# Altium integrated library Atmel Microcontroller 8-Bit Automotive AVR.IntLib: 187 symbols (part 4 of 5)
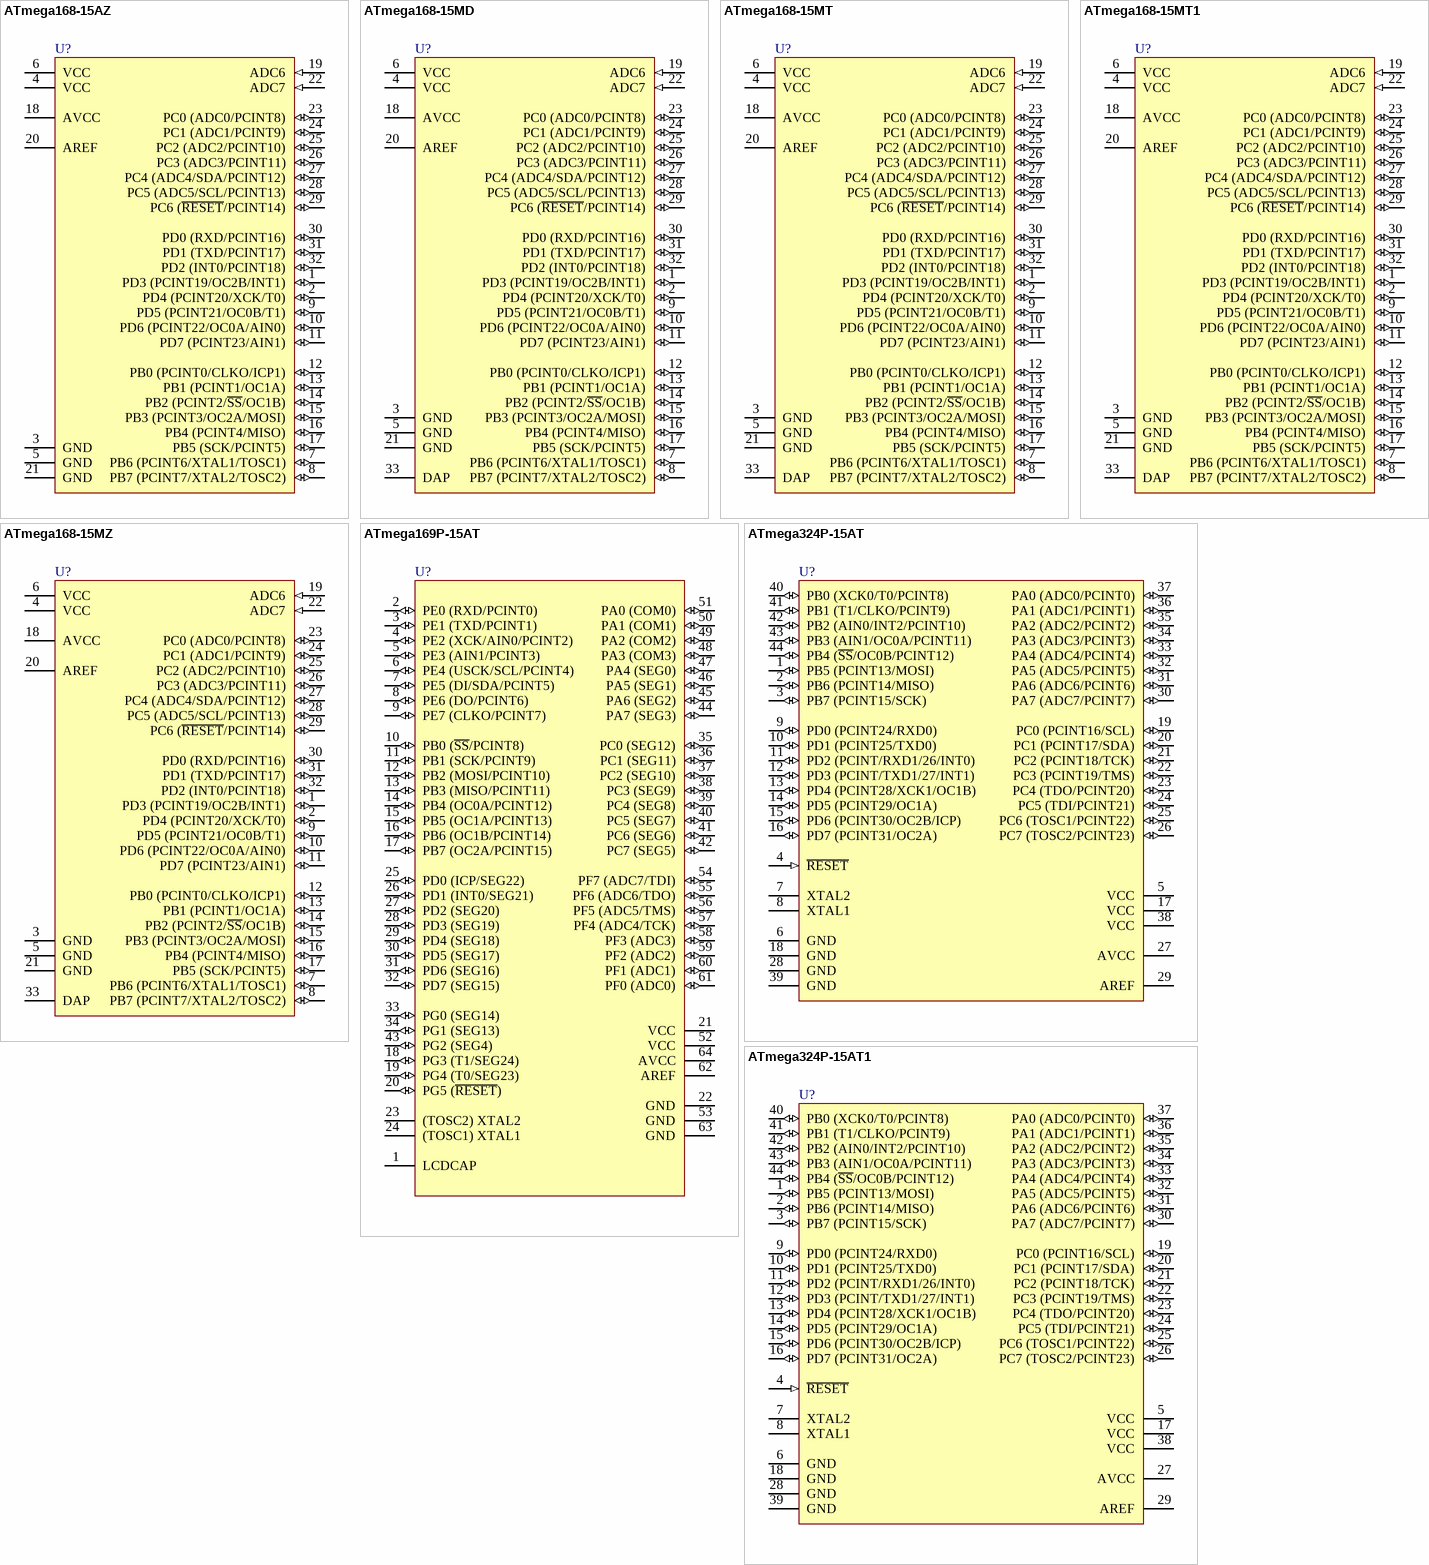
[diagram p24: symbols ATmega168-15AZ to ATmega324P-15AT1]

## ATmega168-15MT
designator U?
8-bit Automotive AVR Microcontroller, 16KB Flash, 512 Bytes EEPROM, 1KB SRAM, Automotive Grade (-40°C to +85°C), 32-Pin VQFN
footprint 32PN_N (QFN, 32-Leads, Body 5x5mm, Pitch 0.5mm, IPC Medium Density)
footprint 32PN_L (QFN, 32-Leads, Body 5x5mm, Pitch 0.5mm, IPC High Density)
footprint 32PN_M (QFN, 32-Leads, Body 5x5mm, Pitch 0.5mm, IPC Low Density)
pins: 1 PD3 (PCINT19/OC2B/INT1) (io), 2 PD4 (PCINT20/XCK/T0) (io), 3 GND (power), 4 VCC (power), 5 GND (power), 6 VCC (power), 7 PB6 (PCINT6/XTAL1/TOSC1) (io), 8 PB7 (PCINT7/XTAL2/TOSC2) (io), 9 PD5 (PCINT21/OC0B/T1) (io), 10 PD6 (PCINT22/OC0A/AIN0) (io), 11 PD7 (PCINT23/AIN1) (io), 12 PB0 (PCINT0/CLKO/ICP1) (io), 13 PB1 (PCINT1/OC1A) (io), 14 PB2 (PCINT2/~{SS}/OC1B) (io), 15 PB3 (PCINT3/OC2A/MOSI) (io), 16 PB4 (PCINT4/MISO) (io), 17 PB5 (SCK/PCINT5) (io), 18 AVCC (power), 19 ADC6 (in), 20 AREF, 21 GND (power), 22 ADC7 (in), 23 PC0 (ADC0/PCINT8) (io), 24 PC1 (ADC1/PCINT9) (io), 25 PC2 (ADC2/PCINT10) (io), 26 PC3 (ADC3/PCINT11) (io), 27 PC4 (ADC4/SDA/PCINT12) (io), 28 PC5 (ADC5/SCL/PCINT13) (io), 29 PC6 (~{RESET}/PCINT14) (io), 30 PD0 (RXD/PCINT16) (io), 31 PD1 (TXD/PCINT17) (io), 32 PD2 (INT0/PCINT18) (io), 33 DAP (power)

## ATmega168-15MT1
designator U?
8-bit Automotive AVR Microcontroller, 16KB Flash, 512 Bytes EEPROM, 1KB SRAM, Automotive Grade (-40°C to +105°C), 32-Pin VQFN
footprint 32PN_N (QFN, 32-Leads, Body 5x5mm, Pitch 0.5mm, IPC Medium Density)
footprint 32PN_L (QFN, 32-Leads, Body 5x5mm, Pitch 0.5mm, IPC High Density)
footprint 32PN_M (QFN, 32-Leads, Body 5x5mm, Pitch 0.5mm, IPC Low Density)
pins: 1 PD3 (PCINT19/OC2B/INT1) (io), 2 PD4 (PCINT20/XCK/T0) (io), 3 GND (power), 4 VCC (power), 5 GND (power), 6 VCC (power), 7 PB6 (PCINT6/XTAL1/TOSC1) (io), 8 PB7 (PCINT7/XTAL2/TOSC2) (io), 9 PD5 (PCINT21/OC0B/T1) (io), 10 PD6 (PCINT22/OC0A/AIN0) (io), 11 PD7 (PCINT23/AIN1) (io), 12 PB0 (PCINT0/CLKO/ICP1) (io), 13 PB1 (PCINT1/OC1A) (io), 14 PB2 (PCINT2/~{SS}/OC1B) (io), 15 PB3 (PCINT3/OC2A/MOSI) (io), 16 PB4 (PCINT4/MISO) (io), 17 PB5 (SCK/PCINT5) (io), 18 AVCC (power), 19 ADC6 (in), 20 AREF, 21 GND (power), 22 ADC7 (in), 23 PC0 (ADC0/PCINT8) (io), 24 PC1 (ADC1/PCINT9) (io), 25 PC2 (ADC2/PCINT10) (io), 26 PC3 (ADC3/PCINT11) (io), 27 PC4 (ADC4/SDA/PCINT12) (io), 28 PC5 (ADC5/SCL/PCINT13) (io), 29 PC6 (~{RESET}/PCINT14) (io), 30 PD0 (RXD/PCINT16) (io), 31 PD1 (TXD/PCINT17) (io), 32 PD2 (INT0/PCINT18) (io), 33 DAP (power)

## ATmega168-15MZ
designator U?
8-bit Automotive AVR Microcontroller, 16KB Flash, 512 Bytes EEPROM, 1KB SRAM, Automotive Grade (-40°C to 125°C), 32-Pin VQFN
footprint 32PN_N (QFN, 32-Leads, Body 5x5mm, Pitch 0.5mm, IPC Medium Density)
footprint 32PN_L (QFN, 32-Leads, Body 5x5mm, Pitch 0.5mm, IPC High Density)
footprint 32PN_M (QFN, 32-Leads, Body 5x5mm, Pitch 0.5mm, IPC Low Density)
pins: 1 PD3 (PCINT19/OC2B/INT1) (io), 2 PD4 (PCINT20/XCK/T0) (io), 3 GND (power), 4 VCC (power), 5 GND (power), 6 VCC (power), 7 PB6 (PCINT6/XTAL1/TOSC1) (io), 8 PB7 (PCINT7/XTAL2/TOSC2) (io), 9 PD5 (PCINT21/OC0B/T1) (io), 10 PD6 (PCINT22/OC0A/AIN0) (io), 11 PD7 (PCINT23/AIN1) (io), 12 PB0 (PCINT0/CLKO/ICP1) (io), 13 PB1 (PCINT1/OC1A) (io), 14 PB2 (PCINT2/~{SS}/OC1B) (io), 15 PB3 (PCINT3/OC2A/MOSI) (io), 16 PB4 (PCINT4/MISO) (io), 17 PB5 (SCK/PCINT5) (io), 18 AVCC (power), 19 ADC6 (in), 20 AREF, 21 GND (power), 22 ADC7 (in), 23 PC0 (ADC0/PCINT8) (io), 24 PC1 (ADC1/PCINT9) (io), 25 PC2 (ADC2/PCINT10) (io), 26 PC3 (ADC3/PCINT11) (io), 27 PC4 (ADC4/SDA/PCINT12) (io), 28 PC5 (ADC5/SCL/PCINT13) (io), 29 PC6 (~{RESET}/PCINT14) (io), 30 PD0 (RXD/PCINT16) (io), 31 PD1 (TXD/PCINT17) (io), 32 PD2 (INT0/PCINT18) (io), 33 DAP (power)

## ATmega169P-15AT
designator U?
8-bit Automotive AVR Microcontroller, 16KB Flash, 512 Bytes EEPROM, 1KB SRAM, Automotive Quality (-40°C to 85°C), 64-pin TQFP
footprint 64MD_N (Thin QFP, 64-Leads, Body 14x14mm, Pitch 0.8mm, IPC Medium Density)
footprint 64MD_L (Thin QFP, 64-Leads, Body 14x14mm, Pitch 0.8mm, IPC High Density)
footprint 64MD_M (Thin QFP, 64-Leads, Body 14x14mm, Pitch 0.8mm, IPC Low Density)
pins: 1 LCDCAP, 2 PE0 (RXD/PCINT0) (io), 3 PE1 (TXD/PCINT1) (io), 4 PE2 (XCK/AIN0/PCINT2) (io), 5 PE3 (AIN1/PCINT3) (io), 6 PE4 (USCK/SCL/PCINT4) (io), 7 PE5 (DI/SDA/PCINT5) (io), 8 PE6 (DO/PCINT6) (io), 9 PE7 (CLKO/PCINT7) (io), 10 PB0 (~{SS}/PCINT8) (io), 11 PB1 (SCK/PCINT9) (io), 12 PB2 (MOSI/PCINT10) (io), 13 PB3 (MISO/PCINT11) (io), 14 PB4 (OC0A/PCINT12) (io), 15 PB5 (OC1A/PCINT13) (io), 16 PB6 (OC1B/PCINT14) (io), 17 PB7 (OC2A/PCINT15) (io), 18 PG3 (T1/SEG24) (io), 19 PG4 (T0/SEG23) (io), 20 PG5 (~{RESET}) (io), 21 VCC (power), 22 GND (power), 23 (TOSC2) XTAL2, 24 (TOSC1) XTAL1, 25 PD0 (ICP/SEG22) (io), 26 PD1 (INT0/SEG21) (io), 27 PD2 (SEG20) (io), 28 PD3 (SEG19) (io), 29 PD4 (SEG18) (io), 30 PD5 (SEG17) (io), 31 PD6 (SEG16) (io), 32 PD7 (SEG15) (io), 33 PG0 (SEG14) (io), 34 PG1 (SEG13) (io), 35 PC0 (SEG12) (io), 36 PC1 (SEG11) (io), 37 PC2 (SEG10) (io), 38 PC3 (SEG9) (io), 39 PC4 (SEG8) (io), 40 PC5 (SEG7) (io), 41 PC6 (SEG6) (io), 42 PC7 (SEG5) (io), 43 PG2 (SEG4) (io), 44 PA7 (SEG3) (io), 45 PA6 (SEG2) (io), 46 PA5 (SEG1) (io), 47 PA4 (SEG0) (io), 48 PA3 (COM3) (io), 49 PA2 (COM2) (io), 50 PA1 (COM1) (io), 51 PA0 (COM0) (io), 52 VCC (power), 53 GND (power), 54 PF7 (ADC7/TDI) (io), 55 PF6 (ADC6/TDO) (io), 56 PF5 (ADC5/TMS) (io), 57 PF4 (ADC4/TCK) (io), 58 PF3 (ADC3) (io), 59 PF2 (ADC2) (io), 60 PF1 (ADC1) (io), 61 PF0 (ADC0) (io), 62 AREF, 63 GND (power), 64 AVCC (power)

## ATmega324P-15AT
designator U?
8-bit Automotive AVR Microcontroller, 32KB Flash, 1KB EEPROM, 2KB SRAM, Automotive Quality (-40°C to +85°C), 44-Pin TQFP
footprint 44ML_N (Thin QFP, 44-Leads, Body 10x10mm, Pitch 0.8mm, IPC Medium Density)
footprint 44ML_L (Thin QFP, 44-Leads, Body 10x10mm, Pitch 0.8mm, IPC High Density)
footprint 44ML_M (Thin QFP, 44-Leads, Body 10x10mm, Pitch 0.8mm, IPC Low Density)
pins: 1 PB5 (PCINT13/MOSI) (io), 2 PB6 (PCINT14/MISO) (io), 3 PB7 (PCINT15/SCK) (io), 4 ~{RESET} (in), 5 VCC (power), 6 GND (power), 7 XTAL2, 8 XTAL1, 9 PD0 (PCINT24/RXD0) (io), 10 PD1 (PCINT25/TXD0) (io), 11 PD2 (PCINT/RXD1/26/INT0) (io), 12 PD3 (PCINT/TXD1/27/INT1) (io), 13 PD4 (PCINT28/XCK1/OC1B) (io), 14 PD5 (PCINT29/OC1A) (io), 15 PD6 (PCINT30/OC2B/ICP) (io), 16 PD7 (PCINT31/OC2A) (io), 17 VCC (power), 18 GND (power), 19 PC0 (PCINT16/SCL) (io), 20 PC1 (PCINT17/SDA) (io), 21 PC2 (PCINT18/TCK) (io), 22 PC3 (PCINT19/TMS) (io), 23 PC4 (TDO/PCINT20) (io), 24 PC5 (TDI/PCINT21) (io), 25 PC6 (TOSC1/PCINT22) (io), 26 PC7 (TOSC2/PCINT23) (io), 27 AVCC (power), 28 GND (power), 29 AREF (power), 30 PA7 (ADC7/PCINT7) (io), 31 PA6 (ADC6/PCINT6) (io), 32 PA5 (ADC5/PCINT5) (io), 33 PA4 (ADC4/PCINT4) (io), 34 PA3 (ADC3/PCINT3) (io), 35 PA2 (ADC2/PCINT2) (io), 36 PA1 (ADC1/PCINT1) (io), 37 PA0 (ADC0/PCINT0) (io), 38 VCC (power), 39 GND (power), 40 PB0 (XCK0/T0/PCINT8) (io), 41 PB1 (T1/CLKO/PCINT9) (io), 42 PB2 (AIN0/INT2/PCINT10) (io), 43 PB3 (AIN1/OC0A/PCINT11) (io), 44 PB4 (~{SS}/OC0B/PCINT12) (io)

## ATmega324P-15AT1
designator U?
8-bit Automotive AVR Microcontroller, 32KB Flash, 1KB EEPROM, 2KB SRAM, Reduced Automotive Grade (-40°C to +105°C), 44-Pin TQFP
footprint 44ML_N (Thin QFP, 44-Leads, Body 10x10mm, Pitch 0.8mm, IPC Medium Density)
footprint 44ML_L (Thin QFP, 44-Leads, Body 10x10mm, Pitch 0.8mm, IPC High Density)
footprint 44ML_M (Thin QFP, 44-Leads, Body 10x10mm, Pitch 0.8mm, IPC Low Density)
pins: 1 PB5 (PCINT13/MOSI) (io), 2 PB6 (PCINT14/MISO) (io), 3 PB7 (PCINT15/SCK) (io), 4 ~{RESET} (in), 5 VCC (power), 6 GND (power), 7 XTAL2, 8 XTAL1, 9 PD0 (PCINT24/RXD0) (io), 10 PD1 (PCINT25/TXD0) (io), 11 PD2 (PCINT/RXD1/26/INT0) (io), 12 PD3 (PCINT/TXD1/27/INT1) (io), 13 PD4 (PCINT28/XCK1/OC1B) (io), 14 PD5 (PCINT29/OC1A) (io), 15 PD6 (PCINT30/OC2B/ICP) (io), 16 PD7 (PCINT31/OC2A) (io), 17 VCC (power), 18 GND (power), 19 PC0 (PCINT16/SCL) (io), 20 PC1 (PCINT17/SDA) (io), 21 PC2 (PCINT18/TCK) (io), 22 PC3 (PCINT19/TMS) (io), 23 PC4 (TDO/PCINT20) (io), 24 PC5 (TDI/PCINT21) (io), 25 PC6 (TOSC1/PCINT22) (io), 26 PC7 (TOSC2/PCINT23) (io), 27 AVCC (power), 28 GND (power), 29 AREF (power), 30 PA7 (ADC7/PCINT7) (io), 31 PA6 (ADC6/PCINT6) (io), 32 PA5 (ADC5/PCINT5) (io), 33 PA4 (ADC4/PCINT4) (io), 34 PA3 (ADC3/PCINT3) (io), 35 PA2 (ADC2/PCINT2) (io), 36 PA1 (ADC1/PCINT1) (io), 37 PA0 (ADC0/PCINT0) (io), 38 VCC (power), 39 GND (power), 40 PB0 (XCK0/T0/PCINT8) (io), 41 PB1 (T1/CLKO/PCINT9) (io), 42 PB2 (AIN0/INT2/PCINT10) (io), 43 PB3 (AIN1/OC0A/PCINT11) (io), 44 PB4 (~{SS}/OC0B/PCINT12) (io)

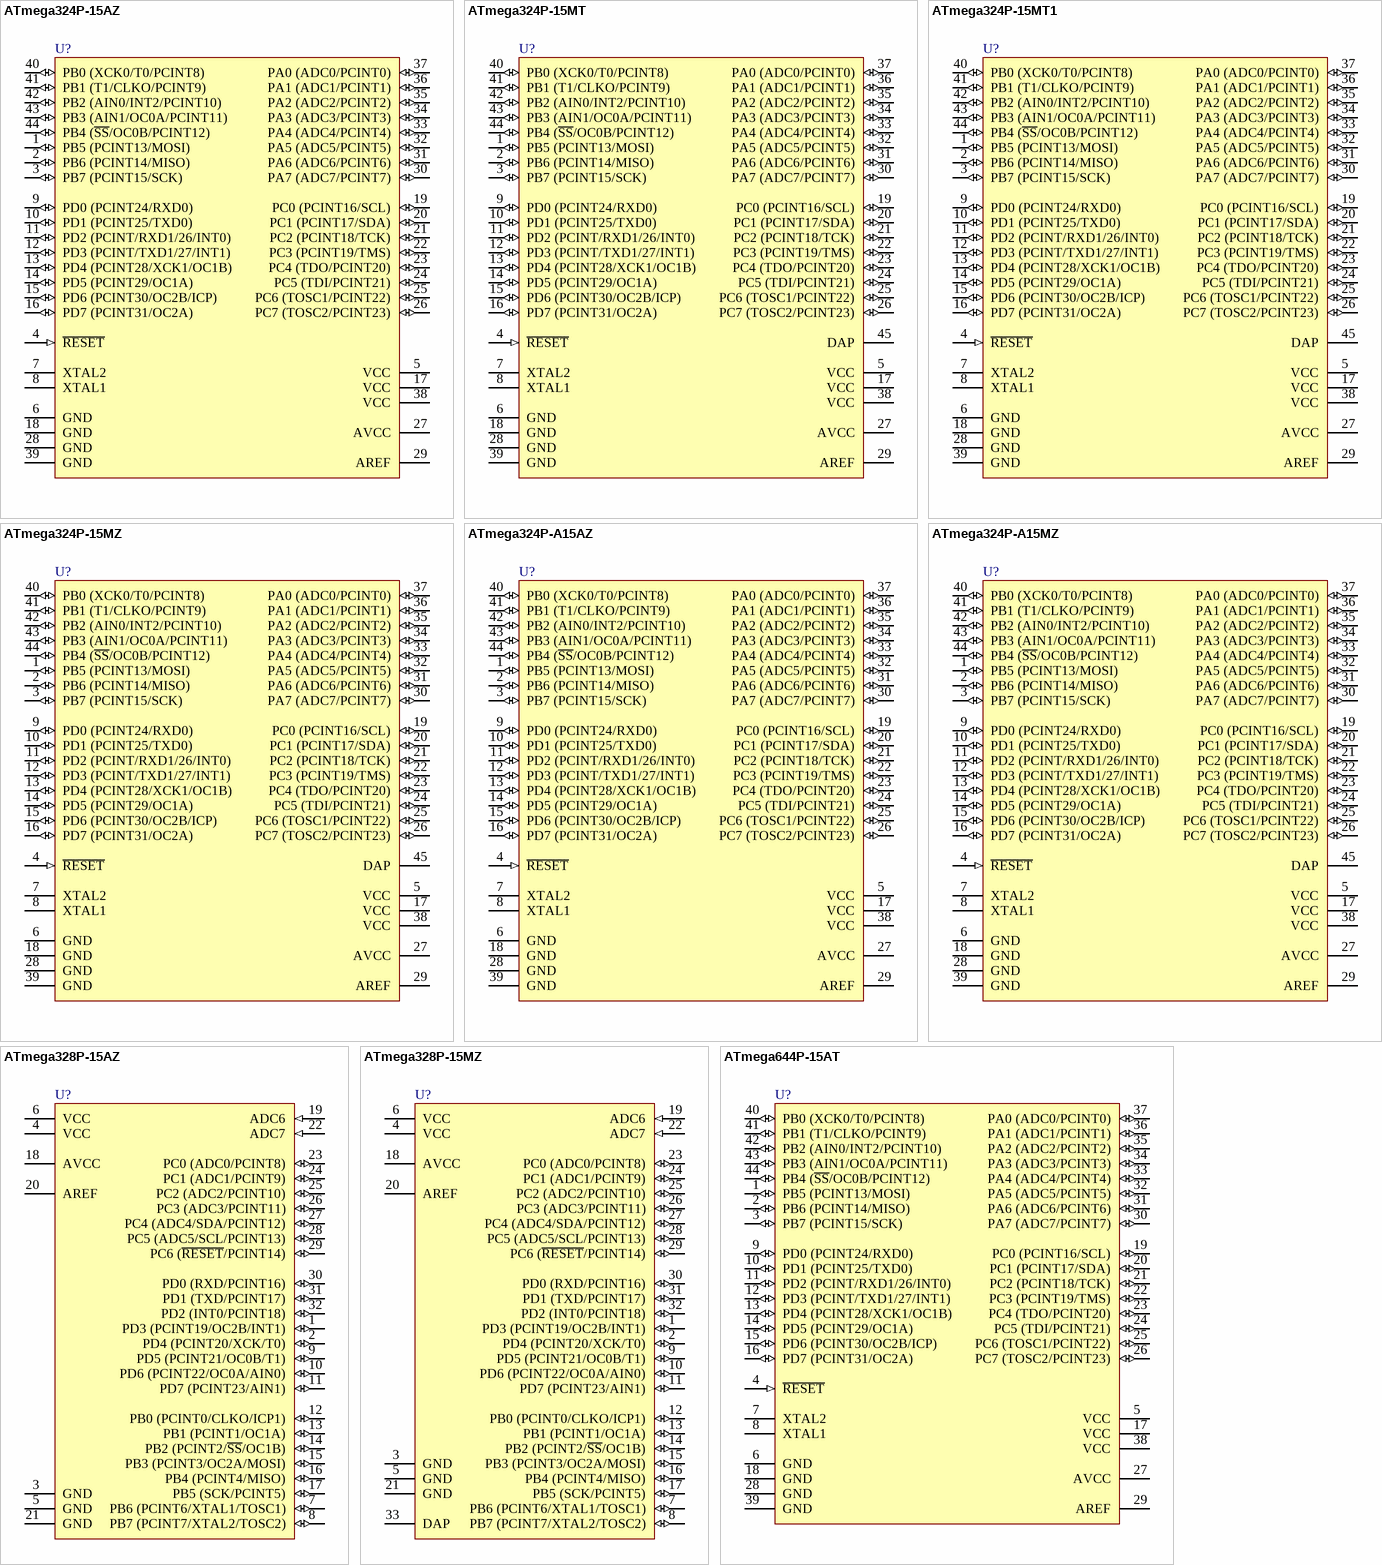
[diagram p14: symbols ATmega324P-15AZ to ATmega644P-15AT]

## ATmega324P-15AZ
designator U?
8-bit Automotive AVR Microcontroller, 32KB Flash, 1KB EEPROM, 2KB SRAM, Automotive Grade (-40°C to +125°C), 44-Pin TQFP
footprint 44ML_N (Thin QFP, 44-Leads, Body 10x10mm, Pitch 0.8mm, IPC Medium Density)
footprint 44ML_L (Thin QFP, 44-Leads, Body 10x10mm, Pitch 0.8mm, IPC High Density)
footprint 44ML_M (Thin QFP, 44-Leads, Body 10x10mm, Pitch 0.8mm, IPC Low Density)
pins: 1 PB5 (PCINT13/MOSI) (io), 2 PB6 (PCINT14/MISO) (io), 3 PB7 (PCINT15/SCK) (io), 4 ~{RESET} (in), 5 VCC (power), 6 GND (power), 7 XTAL2, 8 XTAL1, 9 PD0 (PCINT24/RXD0) (io), 10 PD1 (PCINT25/TXD0) (io), 11 PD2 (PCINT/RXD1/26/INT0) (io), 12 PD3 (PCINT/TXD1/27/INT1) (io), 13 PD4 (PCINT28/XCK1/OC1B) (io), 14 PD5 (PCINT29/OC1A) (io), 15 PD6 (PCINT30/OC2B/ICP) (io), 16 PD7 (PCINT31/OC2A) (io), 17 VCC (power), 18 GND (power), 19 PC0 (PCINT16/SCL) (io), 20 PC1 (PCINT17/SDA) (io), 21 PC2 (PCINT18/TCK) (io), 22 PC3 (PCINT19/TMS) (io), 23 PC4 (TDO/PCINT20) (io), 24 PC5 (TDI/PCINT21) (io), 25 PC6 (TOSC1/PCINT22) (io), 26 PC7 (TOSC2/PCINT23) (io), 27 AVCC (power), 28 GND (power), 29 AREF (power), 30 PA7 (ADC7/PCINT7) (io), 31 PA6 (ADC6/PCINT6) (io), 32 PA5 (ADC5/PCINT5) (io), 33 PA4 (ADC4/PCINT4) (io), 34 PA3 (ADC3/PCINT3) (io), 35 PA2 (ADC2/PCINT2) (io), 36 PA1 (ADC1/PCINT1) (io), 37 PA0 (ADC0/PCINT0) (io), 38 VCC (power), 39 GND (power), 40 PB0 (XCK0/T0/PCINT8) (io), 41 PB1 (T1/CLKO/PCINT9) (io), 42 PB2 (AIN0/INT2/PCINT10) (io), 43 PB3 (AIN1/OC0A/PCINT11) (io), 44 PB4 (~{SS}/OC0B/PCINT12) (io)

## ATmega324P-15MT
designator U?
8-bit Automotive AVR Microcontroller, 32KB Flash, 1KB EEPROM, 2KB SRAM, Automotive Quality (-40°C to +85°C), 44-Pin VQFN
footprint 44PW_N (QFN, 44-Leads, Body 7x7mm, Pitch 0.5mm, IPC Medium Density)
footprint 44PW_L (QFN, 44-Leads, Body 7x7mm, Pitch 0.5mm, IPC High Density)
footprint 44PW_M (QFN, 44-Leads, Body 7x7mm, Pitch 0.5mm, IPC Low Density)
pins: 1 PB5 (PCINT13/MOSI) (io), 2 PB6 (PCINT14/MISO) (io), 3 PB7 (PCINT15/SCK) (io), 4 ~{RESET} (in), 5 VCC (power), 6 GND (power), 7 XTAL2, 8 XTAL1, 9 PD0 (PCINT24/RXD0) (io), 10 PD1 (PCINT25/TXD0) (io), 11 PD2 (PCINT/RXD1/26/INT0) (io), 12 PD3 (PCINT/TXD1/27/INT1) (io), 13 PD4 (PCINT28/XCK1/OC1B) (io), 14 PD5 (PCINT29/OC1A) (io), 15 PD6 (PCINT30/OC2B/ICP) (io), 16 PD7 (PCINT31/OC2A) (io), 17 VCC (power), 18 GND (power), 19 PC0 (PCINT16/SCL) (io), 20 PC1 (PCINT17/SDA) (io), 21 PC2 (PCINT18/TCK) (io), 22 PC3 (PCINT19/TMS) (io), 23 PC4 (TDO/PCINT20) (io), 24 PC5 (TDI/PCINT21) (io), 25 PC6 (TOSC1/PCINT22) (io), 26 PC7 (TOSC2/PCINT23) (io), 27 AVCC (power), 28 GND (power), 29 AREF, 30 PA7 (ADC7/PCINT7) (io), 31 PA6 (ADC6/PCINT6) (io), 32 PA5 (ADC5/PCINT5) (io), 33 PA4 (ADC4/PCINT4) (io), 34 PA3 (ADC3/PCINT3) (io), 35 PA2 (ADC2/PCINT2) (io), 36 PA1 (ADC1/PCINT1) (io), 37 PA0 (ADC0/PCINT0) (io), 38 VCC (power), 39 GND (power), 40 PB0 (XCK0/T0/PCINT8) (io), 41 PB1 (T1/CLKO/PCINT9) (io), 42 PB2 (AIN0/INT2/PCINT10) (io), 43 PB3 (AIN1/OC0A/PCINT11) (io), 44 PB4 (~{SS}/OC0B/PCINT12) (io), 45 DAP (power)

## ATmega324P-15MT1
designator U?
8-bit Automotive AVR Microcontroller, 32KB Flash, 1KB EEPROM, 2KB SRAM, Reduced Automotive Grade (-40°C to +105°C), 44-Pin VQFN
footprint 44PW_N (QFN, 44-Leads, Body 7x7mm, Pitch 0.5mm, IPC Medium Density)
footprint 44PW_L (QFN, 44-Leads, Body 7x7mm, Pitch 0.5mm, IPC High Density)
footprint 44PW_M (QFN, 44-Leads, Body 7x7mm, Pitch 0.5mm, IPC Low Density)
pins: 1 PB5 (PCINT13/MOSI) (io), 2 PB6 (PCINT14/MISO) (io), 3 PB7 (PCINT15/SCK) (io), 4 ~{RESET} (in), 5 VCC (power), 6 GND (power), 7 XTAL2, 8 XTAL1, 9 PD0 (PCINT24/RXD0) (io), 10 PD1 (PCINT25/TXD0) (io), 11 PD2 (PCINT/RXD1/26/INT0) (io), 12 PD3 (PCINT/TXD1/27/INT1) (io), 13 PD4 (PCINT28/XCK1/OC1B) (io), 14 PD5 (PCINT29/OC1A) (io), 15 PD6 (PCINT30/OC2B/ICP) (io), 16 PD7 (PCINT31/OC2A) (io), 17 VCC (power), 18 GND (power), 19 PC0 (PCINT16/SCL) (io), 20 PC1 (PCINT17/SDA) (io), 21 PC2 (PCINT18/TCK) (io), 22 PC3 (PCINT19/TMS) (io), 23 PC4 (TDO/PCINT20) (io), 24 PC5 (TDI/PCINT21) (io), 25 PC6 (TOSC1/PCINT22) (io), 26 PC7 (TOSC2/PCINT23) (io), 27 AVCC (power), 28 GND (power), 29 AREF, 30 PA7 (ADC7/PCINT7) (io), 31 PA6 (ADC6/PCINT6) (io), 32 PA5 (ADC5/PCINT5) (io), 33 PA4 (ADC4/PCINT4) (io), 34 PA3 (ADC3/PCINT3) (io), 35 PA2 (ADC2/PCINT2) (io), 36 PA1 (ADC1/PCINT1) (io), 37 PA0 (ADC0/PCINT0) (io), 38 VCC (power), 39 GND (power), 40 PB0 (XCK0/T0/PCINT8) (io), 41 PB1 (T1/CLKO/PCINT9) (io), 42 PB2 (AIN0/INT2/PCINT10) (io), 43 PB3 (AIN1/OC0A/PCINT11) (io), 44 PB4 (~{SS}/OC0B/PCINT12) (io), 45 DAP (power)

## ATmega324P-15MZ
designator U?
8-bit Automotive AVR Microcontroller, 32KB Flash, 1KB EEPROM, 2KB SRAM, Automotive Grade (-40°C to +125°C), 44-Pin VQFN
footprint 44PW_N (QFN, 44-Leads, Body 7x7mm, Pitch 0.5mm, IPC Medium Density)
footprint 44PW_L (QFN, 44-Leads, Body 7x7mm, Pitch 0.5mm, IPC High Density)
footprint 44PW_M (QFN, 44-Leads, Body 7x7mm, Pitch 0.5mm, IPC Low Density)
pins: 1 PB5 (PCINT13/MOSI) (io), 2 PB6 (PCINT14/MISO) (io), 3 PB7 (PCINT15/SCK) (io), 4 ~{RESET} (in), 5 VCC (power), 6 GND (power), 7 XTAL2, 8 XTAL1, 9 PD0 (PCINT24/RXD0) (io), 10 PD1 (PCINT25/TXD0) (io), 11 PD2 (PCINT/RXD1/26/INT0) (io), 12 PD3 (PCINT/TXD1/27/INT1) (io), 13 PD4 (PCINT28/XCK1/OC1B) (io), 14 PD5 (PCINT29/OC1A) (io), 15 PD6 (PCINT30/OC2B/ICP) (io), 16 PD7 (PCINT31/OC2A) (io), 17 VCC (power), 18 GND (power), 19 PC0 (PCINT16/SCL) (io), 20 PC1 (PCINT17/SDA) (io), 21 PC2 (PCINT18/TCK) (io), 22 PC3 (PCINT19/TMS) (io), 23 PC4 (TDO/PCINT20) (io), 24 PC5 (TDI/PCINT21) (io), 25 PC6 (TOSC1/PCINT22) (io), 26 PC7 (TOSC2/PCINT23) (io), 27 AVCC (power), 28 GND (power), 29 AREF, 30 PA7 (ADC7/PCINT7) (io), 31 PA6 (ADC6/PCINT6) (io), 32 PA5 (ADC5/PCINT5) (io), 33 PA4 (ADC4/PCINT4) (io), 34 PA3 (ADC3/PCINT3) (io), 35 PA2 (ADC2/PCINT2) (io), 36 PA1 (ADC1/PCINT1) (io), 37 PA0 (ADC0/PCINT0) (io), 38 VCC (power), 39 GND (power), 40 PB0 (XCK0/T0/PCINT8) (io), 41 PB1 (T1/CLKO/PCINT9) (io), 42 PB2 (AIN0/INT2/PCINT10) (io), 43 PB3 (AIN1/OC0A/PCINT11) (io), 44 PB4 (~{SS}/OC0B/PCINT12) (io), 45 DAP (power)

## ATmega324P-A15AZ
designator U?
8-bit Automotive AVR Microcontroller, 32KB Flash, 1KB EEPROM, 2KB SRAM, Automotive Grade (-40°C to +125°C), 44-Pin TQFP
footprint 44ML_N (Thin QFP, 44-Leads, Body 10x10mm, Pitch 0.8mm, IPC Medium Density)
footprint 44ML_L (Thin QFP, 44-Leads, Body 10x10mm, Pitch 0.8mm, IPC High Density)
footprint 44ML_M (Thin QFP, 44-Leads, Body 10x10mm, Pitch 0.8mm, IPC Low Density)
pins: 1 PB5 (PCINT13/MOSI) (io), 2 PB6 (PCINT14/MISO) (io), 3 PB7 (PCINT15/SCK) (io), 4 ~{RESET} (in), 5 VCC (power), 6 GND (power), 7 XTAL2, 8 XTAL1, 9 PD0 (PCINT24/RXD0) (io), 10 PD1 (PCINT25/TXD0) (io), 11 PD2 (PCINT/RXD1/26/INT0) (io), 12 PD3 (PCINT/TXD1/27/INT1) (io), 13 PD4 (PCINT28/XCK1/OC1B) (io), 14 PD5 (PCINT29/OC1A) (io), 15 PD6 (PCINT30/OC2B/ICP) (io), 16 PD7 (PCINT31/OC2A) (io), 17 VCC (power), 18 GND (power), 19 PC0 (PCINT16/SCL) (io), 20 PC1 (PCINT17/SDA) (io), 21 PC2 (PCINT18/TCK) (io), 22 PC3 (PCINT19/TMS) (io), 23 PC4 (TDO/PCINT20) (io), 24 PC5 (TDI/PCINT21) (io), 25 PC6 (TOSC1/PCINT22) (io), 26 PC7 (TOSC2/PCINT23) (io), 27 AVCC (power), 28 GND (power), 29 AREF (power), 30 PA7 (ADC7/PCINT7) (io), 31 PA6 (ADC6/PCINT6) (io), 32 PA5 (ADC5/PCINT5) (io), 33 PA4 (ADC4/PCINT4) (io), 34 PA3 (ADC3/PCINT3) (io), 35 PA2 (ADC2/PCINT2) (io), 36 PA1 (ADC1/PCINT1) (io), 37 PA0 (ADC0/PCINT0) (io), 38 VCC (power), 39 GND (power), 40 PB0 (XCK0/T0/PCINT8) (io), 41 PB1 (T1/CLKO/PCINT9) (io), 42 PB2 (AIN0/INT2/PCINT10) (io), 43 PB3 (AIN1/OC0A/PCINT11) (io), 44 PB4 (~{SS}/OC0B/PCINT12) (io)

## ATmega324P-A15MZ
designator U?
8-bit Automotive AVR Microcontroller, 32KB Flash, 1KB EEPROM, 2KB SRAM, Automotive Grade (-40°C to +125°C), 44-Pin VQFN
footprint 44PW_N (QFN, 44-Leads, Body 7x7mm, Pitch 0.5mm, IPC Medium Density)
footprint 44PW_L (QFN, 44-Leads, Body 7x7mm, Pitch 0.5mm, IPC High Density)
footprint 44PW_M (QFN, 44-Leads, Body 7x7mm, Pitch 0.5mm, IPC Low Density)
pins: 1 PB5 (PCINT13/MOSI) (io), 2 PB6 (PCINT14/MISO) (io), 3 PB7 (PCINT15/SCK) (io), 4 ~{RESET} (in), 5 VCC (power), 6 GND (power), 7 XTAL2, 8 XTAL1, 9 PD0 (PCINT24/RXD0) (io), 10 PD1 (PCINT25/TXD0) (io), 11 PD2 (PCINT/RXD1/26/INT0) (io), 12 PD3 (PCINT/TXD1/27/INT1) (io), 13 PD4 (PCINT28/XCK1/OC1B) (io), 14 PD5 (PCINT29/OC1A) (io), 15 PD6 (PCINT30/OC2B/ICP) (io), 16 PD7 (PCINT31/OC2A) (io), 17 VCC (power), 18 GND (power), 19 PC0 (PCINT16/SCL) (io), 20 PC1 (PCINT17/SDA) (io), 21 PC2 (PCINT18/TCK) (io), 22 PC3 (PCINT19/TMS) (io), 23 PC4 (TDO/PCINT20) (io), 24 PC5 (TDI/PCINT21) (io), 25 PC6 (TOSC1/PCINT22) (io), 26 PC7 (TOSC2/PCINT23) (io), 27 AVCC (power), 28 GND (power), 29 AREF, 30 PA7 (ADC7/PCINT7) (io), 31 PA6 (ADC6/PCINT6) (io), 32 PA5 (ADC5/PCINT5) (io), 33 PA4 (ADC4/PCINT4) (io), 34 PA3 (ADC3/PCINT3) (io), 35 PA2 (ADC2/PCINT2) (io), 36 PA1 (ADC1/PCINT1) (io), 37 PA0 (ADC0/PCINT0) (io), 38 VCC (power), 39 GND (power), 40 PB0 (XCK0/T0/PCINT8) (io), 41 PB1 (T1/CLKO/PCINT9) (io), 42 PB2 (AIN0/INT2/PCINT10) (io), 43 PB3 (AIN1/OC0A/PCINT11) (io), 44 PB4 (~{SS}/OC0B/PCINT12) (io), 45 DAP (power)

## ATmega328P-15AZ
designator U?
8-bit Automotive AVR Microcontroller, 32KB Flash, 1KB EEPROM, 2KB SRAM, 23 GPIO pins, Automotive Grade (-40°C to +125°C), 32-Pin TQFP
footprint 32MA_N (Thin QFP, 32-Leads, Body 7x7mm, Pitch 0.8mm, IPC Medium Density)
footprint 32MA_L (Thin QFP, 32-Leads, Body 7x7mm, Pitch 0.8mm, IPC High Density)
footprint 32MA_M (Thin QFP, 32-Leads, Body 7x7mm, Pitch 0.8mm, IPC Low Density)
pins: 1 PD3 (PCINT19/OC2B/INT1) (io), 2 PD4 (PCINT20/XCK/T0) (io), 3 GND (power), 4 VCC (power), 5 GND (power), 6 VCC (power), 7 PB6 (PCINT6/XTAL1/TOSC1) (io), 8 PB7 (PCINT7/XTAL2/TOSC2) (io), 9 PD5 (PCINT21/OC0B/T1) (io), 10 PD6 (PCINT22/OC0A/AIN0) (io), 11 PD7 (PCINT23/AIN1) (io), 12 PB0 (PCINT0/CLKO/ICP1) (io), 13 PB1 (PCINT1/OC1A) (io), 14 PB2 (PCINT2/~{SS}/OC1B) (io), 15 PB3 (PCINT3/OC2A/MOSI) (io), 16 PB4 (PCINT4/MISO) (io), 17 PB5 (SCK/PCINT5) (io), 18 AVCC (power), 19 ADC6 (in), 20 AREF, 21 GND (power), 22 ADC7 (in), 23 PC0 (ADC0/PCINT8) (io), 24 PC1 (ADC1/PCINT9) (io), 25 PC2 (ADC2/PCINT10) (io), 26 PC3 (ADC3/PCINT11) (io), 27 PC4 (ADC4/SDA/PCINT12) (io), 28 PC5 (ADC5/SCL/PCINT13) (io), 29 PC6 (~{RESET}/PCINT14) (io), 30 PD0 (RXD/PCINT16) (io), 31 PD1 (TXD/PCINT17) (io), 32 PD2 (INT0/PCINT18) (io)

## ATmega328P-15MZ
designator U?
8-bit Automotive AVR Microcontroller, 32KB Flash, 1KB EEPROM, 2KB SRAM, 23 GPIO pins, Automotive Grade (-40°C to +125°C), 32-Pin VQFN
footprint 32PN_N (QFN, 32-Leads, Body 5x5mm, Pitch 0.5mm, IPC Medium Density)
footprint 32PN_L (QFN, 32-Leads, Body 5x5mm, Pitch 0.5mm, IPC High Density)
footprint 32PN_M (QFN, 32-Leads, Body 5x5mm, Pitch 0.5mm, IPC Low Density)
pins: 1 PD3 (PCINT19/OC2B/INT1) (io), 2 PD4 (PCINT20/XCK/T0) (io), 3 GND (power), 4 VCC (power), 5 GND (power), 6 VCC (power), 7 PB6 (PCINT6/XTAL1/TOSC1) (io), 8 PB7 (PCINT7/XTAL2/TOSC2) (io), 9 PD5 (PCINT21/OC0B/T1) (io), 10 PD6 (PCINT22/OC0A/AIN0) (io), 11 PD7 (PCINT23/AIN1) (io), 12 PB0 (PCINT0/CLKO/ICP1) (io), 13 PB1 (PCINT1/OC1A) (io), 14 PB2 (PCINT2/~{SS}/OC1B) (io), 15 PB3 (PCINT3/OC2A/MOSI) (io), 16 PB4 (PCINT4/MISO) (io), 17 PB5 (SCK/PCINT5) (io), 18 AVCC (power), 19 ADC6 (in), 20 AREF, 21 GND (power), 22 ADC7 (in), 23 PC0 (ADC0/PCINT8) (io), 24 PC1 (ADC1/PCINT9) (io), 25 PC2 (ADC2/PCINT10) (io), 26 PC3 (ADC3/PCINT11) (io), 27 PC4 (ADC4/SDA/PCINT12) (io), 28 PC5 (ADC5/SCL/PCINT13) (io), 29 PC6 (~{RESET}/PCINT14) (io), 30 PD0 (RXD/PCINT16) (io), 31 PD1 (TXD/PCINT17) (io), 32 PD2 (INT0/PCINT18) (io), 33 DAP (power)

## ATmega644P-15AT
designator U?
8-bit Automotive AVR Microcontroller, 64KB Flash, 2KB EEPROM, 4KB SRAM, Automotive Quality (-40°C to +85°C), 44-Pin TQFP
footprint 44ML_N (Thin QFP, 44-Leads, Body 10x10mm, Pitch 0.8mm, IPC Medium Density)
footprint 44ML_L (Thin QFP, 44-Leads, Body 10x10mm, Pitch 0.8mm, IPC High Density)
footprint 44ML_M (Thin QFP, 44-Leads, Body 10x10mm, Pitch 0.8mm, IPC Low Density)
pins: 1 PB5 (PCINT13/MOSI) (io), 2 PB6 (PCINT14/MISO) (io), 3 PB7 (PCINT15/SCK) (io), 4 ~{RESET} (in), 5 VCC (power), 6 GND (power), 7 XTAL2, 8 XTAL1, 9 PD0 (PCINT24/RXD0) (io), 10 PD1 (PCINT25/TXD0) (io), 11 PD2 (PCINT/RXD1/26/INT0) (io), 12 PD3 (PCINT/TXD1/27/INT1) (io), 13 PD4 (PCINT28/XCK1/OC1B) (io), 14 PD5 (PCINT29/OC1A) (io), 15 PD6 (PCINT30/OC2B/ICP) (io), 16 PD7 (PCINT31/OC2A) (io), 17 VCC (power), 18 GND (power), 19 PC0 (PCINT16/SCL) (io), 20 PC1 (PCINT17/SDA) (io), 21 PC2 (PCINT18/TCK) (io), 22 PC3 (PCINT19/TMS) (io), 23 PC4 (TDO/PCINT20) (io), 24 PC5 (TDI/PCINT21) (io), 25 PC6 (TOSC1/PCINT22) (io), 26 PC7 (TOSC2/PCINT23) (io), 27 AVCC (power), 28 GND (power), 29 AREF (power), 30 PA7 (ADC7/PCINT7) (io), 31 PA6 (ADC6/PCINT6) (io), 32 PA5 (ADC5/PCINT5) (io), 33 PA4 (ADC4/PCINT4) (io), 34 PA3 (ADC3/PCINT3) (io), 35 PA2 (ADC2/PCINT2) (io), 36 PA1 (ADC1/PCINT1) (io), 37 PA0 (ADC0/PCINT0) (io), 38 VCC (power), 39 GND (power), 40 PB0 (XCK0/T0/PCINT8) (io), 41 PB1 (T1/CLKO/PCINT9) (io), 42 PB2 (AIN0/INT2/PCINT10) (io), 43 PB3 (AIN1/OC0A/PCINT11) (io), 44 PB4 (~{SS}/OC0B/PCINT12) (io)

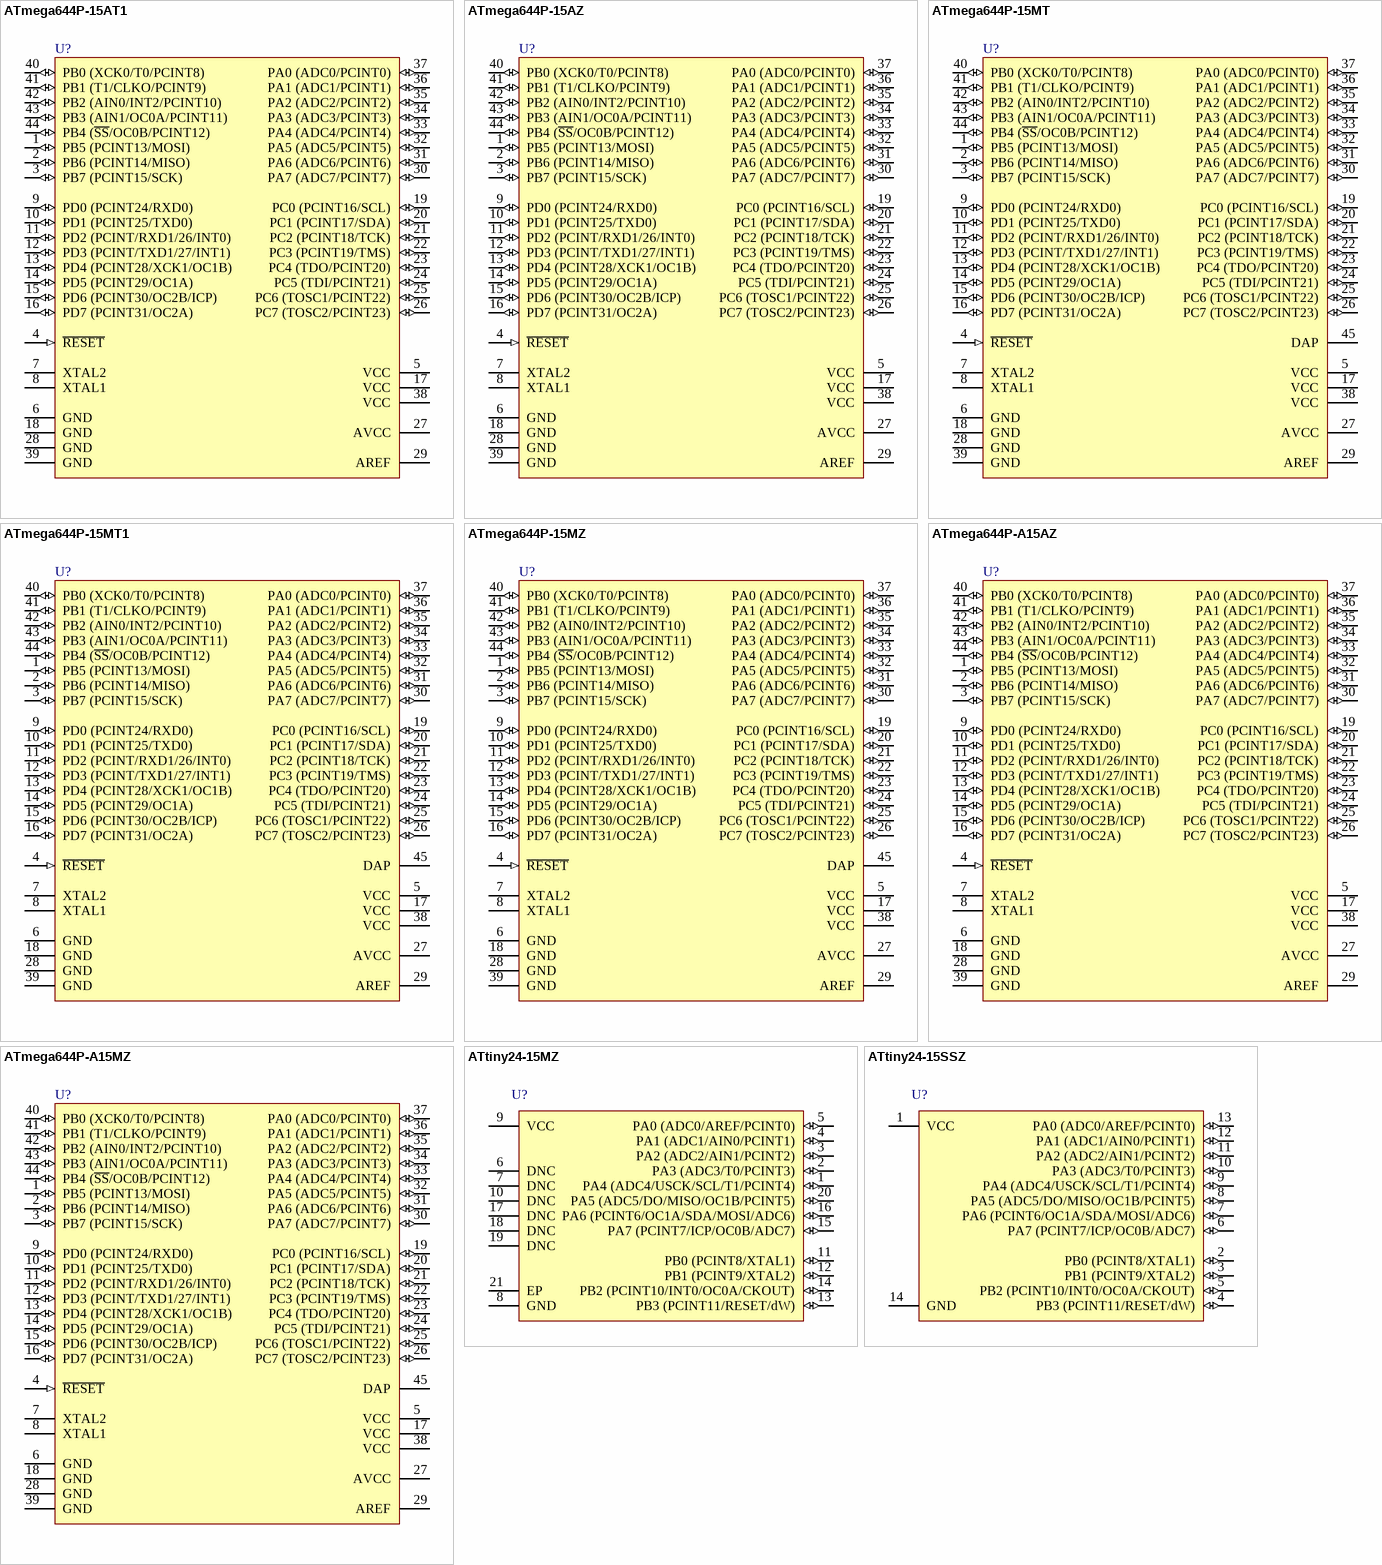
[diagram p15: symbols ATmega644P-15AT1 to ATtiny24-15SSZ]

## ATmega644P-15AT1
designator U?
8-bit Automotive AVR Microcontroller, 64KB Flash, 2KB EEPROM, 4KB SRAM, Reduced Automotive Grade (-40°C to +105°C), 44-Pin TQFP
footprint 44ML_N (Thin QFP, 44-Leads, Body 10x10mm, Pitch 0.8mm, IPC Medium Density)
footprint 44ML_L (Thin QFP, 44-Leads, Body 10x10mm, Pitch 0.8mm, IPC High Density)
footprint 44ML_M (Thin QFP, 44-Leads, Body 10x10mm, Pitch 0.8mm, IPC Low Density)
pins: 1 PB5 (PCINT13/MOSI) (io), 2 PB6 (PCINT14/MISO) (io), 3 PB7 (PCINT15/SCK) (io), 4 ~{RESET} (in), 5 VCC (power), 6 GND (power), 7 XTAL2, 8 XTAL1, 9 PD0 (PCINT24/RXD0) (io), 10 PD1 (PCINT25/TXD0) (io), 11 PD2 (PCINT/RXD1/26/INT0) (io), 12 PD3 (PCINT/TXD1/27/INT1) (io), 13 PD4 (PCINT28/XCK1/OC1B) (io), 14 PD5 (PCINT29/OC1A) (io), 15 PD6 (PCINT30/OC2B/ICP) (io), 16 PD7 (PCINT31/OC2A) (io), 17 VCC (power), 18 GND (power), 19 PC0 (PCINT16/SCL) (io), 20 PC1 (PCINT17/SDA) (io), 21 PC2 (PCINT18/TCK) (io), 22 PC3 (PCINT19/TMS) (io), 23 PC4 (TDO/PCINT20) (io), 24 PC5 (TDI/PCINT21) (io), 25 PC6 (TOSC1/PCINT22) (io), 26 PC7 (TOSC2/PCINT23) (io), 27 AVCC (power), 28 GND (power), 29 AREF (power), 30 PA7 (ADC7/PCINT7) (io), 31 PA6 (ADC6/PCINT6) (io), 32 PA5 (ADC5/PCINT5) (io), 33 PA4 (ADC4/PCINT4) (io), 34 PA3 (ADC3/PCINT3) (io), 35 PA2 (ADC2/PCINT2) (io), 36 PA1 (ADC1/PCINT1) (io), 37 PA0 (ADC0/PCINT0) (io), 38 VCC (power), 39 GND (power), 40 PB0 (XCK0/T0/PCINT8) (io), 41 PB1 (T1/CLKO/PCINT9) (io), 42 PB2 (AIN0/INT2/PCINT10) (io), 43 PB3 (AIN1/OC0A/PCINT11) (io), 44 PB4 (~{SS}/OC0B/PCINT12) (io)

## ATmega644P-15AZ
designator U?
8-bit Automotive AVR Microcontroller, 64KB Flash, 2KB EEPROM, 4KB SRAM, Automotive Grade (-40°C to +125°C), 44-Pin TQFP
footprint 44ML_N (Thin QFP, 44-Leads, Body 10x10mm, Pitch 0.8mm, IPC Medium Density)
footprint 44ML_L (Thin QFP, 44-Leads, Body 10x10mm, Pitch 0.8mm, IPC High Density)
footprint 44ML_M (Thin QFP, 44-Leads, Body 10x10mm, Pitch 0.8mm, IPC Low Density)
pins: 1 PB5 (PCINT13/MOSI) (io), 2 PB6 (PCINT14/MISO) (io), 3 PB7 (PCINT15/SCK) (io), 4 ~{RESET} (in), 5 VCC (power), 6 GND (power), 7 XTAL2, 8 XTAL1, 9 PD0 (PCINT24/RXD0) (io), 10 PD1 (PCINT25/TXD0) (io), 11 PD2 (PCINT/RXD1/26/INT0) (io), 12 PD3 (PCINT/TXD1/27/INT1) (io), 13 PD4 (PCINT28/XCK1/OC1B) (io), 14 PD5 (PCINT29/OC1A) (io), 15 PD6 (PCINT30/OC2B/ICP) (io), 16 PD7 (PCINT31/OC2A) (io), 17 VCC (power), 18 GND (power), 19 PC0 (PCINT16/SCL) (io), 20 PC1 (PCINT17/SDA) (io), 21 PC2 (PCINT18/TCK) (io), 22 PC3 (PCINT19/TMS) (io), 23 PC4 (TDO/PCINT20) (io), 24 PC5 (TDI/PCINT21) (io), 25 PC6 (TOSC1/PCINT22) (io), 26 PC7 (TOSC2/PCINT23) (io), 27 AVCC (power), 28 GND (power), 29 AREF (power), 30 PA7 (ADC7/PCINT7) (io), 31 PA6 (ADC6/PCINT6) (io), 32 PA5 (ADC5/PCINT5) (io), 33 PA4 (ADC4/PCINT4) (io), 34 PA3 (ADC3/PCINT3) (io), 35 PA2 (ADC2/PCINT2) (io), 36 PA1 (ADC1/PCINT1) (io), 37 PA0 (ADC0/PCINT0) (io), 38 VCC (power), 39 GND (power), 40 PB0 (XCK0/T0/PCINT8) (io), 41 PB1 (T1/CLKO/PCINT9) (io), 42 PB2 (AIN0/INT2/PCINT10) (io), 43 PB3 (AIN1/OC0A/PCINT11) (io), 44 PB4 (~{SS}/OC0B/PCINT12) (io)

## ATmega644P-15MT
designator U?
8-bit Automotive AVR Microcontroller, 64KB Flash, 2KB EEPROM, 4KB SRAM, Automotive Quality (-40°C to +85°C), 44-Pin VQFN
footprint 44PW_N (QFN, 44-Leads, Body 7x7mm, Pitch 0.5mm, IPC Medium Density)
footprint 44PW_L (QFN, 44-Leads, Body 7x7mm, Pitch 0.5mm, IPC High Density)
footprint 44PW_M (QFN, 44-Leads, Body 7x7mm, Pitch 0.5mm, IPC Low Density)
pins: 1 PB5 (PCINT13/MOSI) (io), 2 PB6 (PCINT14/MISO) (io), 3 PB7 (PCINT15/SCK) (io), 4 ~{RESET} (in), 5 VCC (power), 6 GND (power), 7 XTAL2, 8 XTAL1, 9 PD0 (PCINT24/RXD0) (io), 10 PD1 (PCINT25/TXD0) (io), 11 PD2 (PCINT/RXD1/26/INT0) (io), 12 PD3 (PCINT/TXD1/27/INT1) (io), 13 PD4 (PCINT28/XCK1/OC1B) (io), 14 PD5 (PCINT29/OC1A) (io), 15 PD6 (PCINT30/OC2B/ICP) (io), 16 PD7 (PCINT31/OC2A) (io), 17 VCC (power), 18 GND (power), 19 PC0 (PCINT16/SCL) (io), 20 PC1 (PCINT17/SDA) (io), 21 PC2 (PCINT18/TCK) (io), 22 PC3 (PCINT19/TMS) (io), 23 PC4 (TDO/PCINT20) (io), 24 PC5 (TDI/PCINT21) (io), 25 PC6 (TOSC1/PCINT22) (io), 26 PC7 (TOSC2/PCINT23) (io), 27 AVCC (power), 28 GND (power), 29 AREF, 30 PA7 (ADC7/PCINT7) (io), 31 PA6 (ADC6/PCINT6) (io), 32 PA5 (ADC5/PCINT5) (io), 33 PA4 (ADC4/PCINT4) (io), 34 PA3 (ADC3/PCINT3) (io), 35 PA2 (ADC2/PCINT2) (io), 36 PA1 (ADC1/PCINT1) (io), 37 PA0 (ADC0/PCINT0) (io), 38 VCC (power), 39 GND (power), 40 PB0 (XCK0/T0/PCINT8) (io), 41 PB1 (T1/CLKO/PCINT9) (io), 42 PB2 (AIN0/INT2/PCINT10) (io), 43 PB3 (AIN1/OC0A/PCINT11) (io), 44 PB4 (~{SS}/OC0B/PCINT12) (io), 45 DAP (power)

## ATmega644P-15MT1
designator U?
8-bit Automotive AVR Microcontroller, 64KB Flash, 2KB EEPROM, 4KB SRAM, Reduced Automotive Grade (-40°C to +105°C), 44-Pin VQFN
footprint 44PW_N (QFN, 44-Leads, Body 7x7mm, Pitch 0.5mm, IPC Medium Density)
footprint 44PW_L (QFN, 44-Leads, Body 7x7mm, Pitch 0.5mm, IPC High Density)
footprint 44PW_M (QFN, 44-Leads, Body 7x7mm, Pitch 0.5mm, IPC Low Density)
pins: 1 PB5 (PCINT13/MOSI) (io), 2 PB6 (PCINT14/MISO) (io), 3 PB7 (PCINT15/SCK) (io), 4 ~{RESET} (in), 5 VCC (power), 6 GND (power), 7 XTAL2, 8 XTAL1, 9 PD0 (PCINT24/RXD0) (io), 10 PD1 (PCINT25/TXD0) (io), 11 PD2 (PCINT/RXD1/26/INT0) (io), 12 PD3 (PCINT/TXD1/27/INT1) (io), 13 PD4 (PCINT28/XCK1/OC1B) (io), 14 PD5 (PCINT29/OC1A) (io), 15 PD6 (PCINT30/OC2B/ICP) (io), 16 PD7 (PCINT31/OC2A) (io), 17 VCC (power), 18 GND (power), 19 PC0 (PCINT16/SCL) (io), 20 PC1 (PCINT17/SDA) (io), 21 PC2 (PCINT18/TCK) (io), 22 PC3 (PCINT19/TMS) (io), 23 PC4 (TDO/PCINT20) (io), 24 PC5 (TDI/PCINT21) (io), 25 PC6 (TOSC1/PCINT22) (io), 26 PC7 (TOSC2/PCINT23) (io), 27 AVCC (power), 28 GND (power), 29 AREF, 30 PA7 (ADC7/PCINT7) (io), 31 PA6 (ADC6/PCINT6) (io), 32 PA5 (ADC5/PCINT5) (io), 33 PA4 (ADC4/PCINT4) (io), 34 PA3 (ADC3/PCINT3) (io), 35 PA2 (ADC2/PCINT2) (io), 36 PA1 (ADC1/PCINT1) (io), 37 PA0 (ADC0/PCINT0) (io), 38 VCC (power), 39 GND (power), 40 PB0 (XCK0/T0/PCINT8) (io), 41 PB1 (T1/CLKO/PCINT9) (io), 42 PB2 (AIN0/INT2/PCINT10) (io), 43 PB3 (AIN1/OC0A/PCINT11) (io), 44 PB4 (~{SS}/OC0B/PCINT12) (io), 45 DAP (power)

## ATmega644P-15MZ
designator U?
8-bit Automotive AVR Microcontroller, 64KB Flash, 2KB EEPROM, 4KB SRAM, Automotive Grade (-40°C to +125°C), 44-Pin VQFN
footprint 44PW_N (QFN, 44-Leads, Body 7x7mm, Pitch 0.5mm, IPC Medium Density)
footprint 44PW_L (QFN, 44-Leads, Body 7x7mm, Pitch 0.5mm, IPC High Density)
footprint 44PW_M (QFN, 44-Leads, Body 7x7mm, Pitch 0.5mm, IPC Low Density)
pins: 1 PB5 (PCINT13/MOSI) (io), 2 PB6 (PCINT14/MISO) (io), 3 PB7 (PCINT15/SCK) (io), 4 ~{RESET} (in), 5 VCC (power), 6 GND (power), 7 XTAL2, 8 XTAL1, 9 PD0 (PCINT24/RXD0) (io), 10 PD1 (PCINT25/TXD0) (io), 11 PD2 (PCINT/RXD1/26/INT0) (io), 12 PD3 (PCINT/TXD1/27/INT1) (io), 13 PD4 (PCINT28/XCK1/OC1B) (io), 14 PD5 (PCINT29/OC1A) (io), 15 PD6 (PCINT30/OC2B/ICP) (io), 16 PD7 (PCINT31/OC2A) (io), 17 VCC (power), 18 GND (power), 19 PC0 (PCINT16/SCL) (io), 20 PC1 (PCINT17/SDA) (io), 21 PC2 (PCINT18/TCK) (io), 22 PC3 (PCINT19/TMS) (io), 23 PC4 (TDO/PCINT20) (io), 24 PC5 (TDI/PCINT21) (io), 25 PC6 (TOSC1/PCINT22) (io), 26 PC7 (TOSC2/PCINT23) (io), 27 AVCC (power), 28 GND (power), 29 AREF, 30 PA7 (ADC7/PCINT7) (io), 31 PA6 (ADC6/PCINT6) (io), 32 PA5 (ADC5/PCINT5) (io), 33 PA4 (ADC4/PCINT4) (io), 34 PA3 (ADC3/PCINT3) (io), 35 PA2 (ADC2/PCINT2) (io), 36 PA1 (ADC1/PCINT1) (io), 37 PA0 (ADC0/PCINT0) (io), 38 VCC (power), 39 GND (power), 40 PB0 (XCK0/T0/PCINT8) (io), 41 PB1 (T1/CLKO/PCINT9) (io), 42 PB2 (AIN0/INT2/PCINT10) (io), 43 PB3 (AIN1/OC0A/PCINT11) (io), 44 PB4 (~{SS}/OC0B/PCINT12) (io), 45 DAP (power)

## ATmega644P-A15AZ
designator U?
8-bit Automotive AVR Microcontroller, 64KB Flash, 2KB EEPROM, 4KB SRAM, Automotive Grade (-40°C to +125°C), 44-Pin TQFP
footprint 44ML_N (Thin QFP, 44-Leads, Body 10x10mm, Pitch 0.8mm, IPC Medium Density)
footprint 44ML_L (Thin QFP, 44-Leads, Body 10x10mm, Pitch 0.8mm, IPC High Density)
footprint 44ML_M (Thin QFP, 44-Leads, Body 10x10mm, Pitch 0.8mm, IPC Low Density)
pins: 1 PB5 (PCINT13/MOSI) (io), 2 PB6 (PCINT14/MISO) (io), 3 PB7 (PCINT15/SCK) (io), 4 ~{RESET} (in), 5 VCC (power), 6 GND (power), 7 XTAL2, 8 XTAL1, 9 PD0 (PCINT24/RXD0) (io), 10 PD1 (PCINT25/TXD0) (io), 11 PD2 (PCINT/RXD1/26/INT0) (io), 12 PD3 (PCINT/TXD1/27/INT1) (io), 13 PD4 (PCINT28/XCK1/OC1B) (io), 14 PD5 (PCINT29/OC1A) (io), 15 PD6 (PCINT30/OC2B/ICP) (io), 16 PD7 (PCINT31/OC2A) (io), 17 VCC (power), 18 GND (power), 19 PC0 (PCINT16/SCL) (io), 20 PC1 (PCINT17/SDA) (io), 21 PC2 (PCINT18/TCK) (io), 22 PC3 (PCINT19/TMS) (io), 23 PC4 (TDO/PCINT20) (io), 24 PC5 (TDI/PCINT21) (io), 25 PC6 (TOSC1/PCINT22) (io), 26 PC7 (TOSC2/PCINT23) (io), 27 AVCC (power), 28 GND (power), 29 AREF (power), 30 PA7 (ADC7/PCINT7) (io), 31 PA6 (ADC6/PCINT6) (io), 32 PA5 (ADC5/PCINT5) (io), 33 PA4 (ADC4/PCINT4) (io), 34 PA3 (ADC3/PCINT3) (io), 35 PA2 (ADC2/PCINT2) (io), 36 PA1 (ADC1/PCINT1) (io), 37 PA0 (ADC0/PCINT0) (io), 38 VCC (power), 39 GND (power), 40 PB0 (XCK0/T0/PCINT8) (io), 41 PB1 (T1/CLKO/PCINT9) (io), 42 PB2 (AIN0/INT2/PCINT10) (io), 43 PB3 (AIN1/OC0A/PCINT11) (io), 44 PB4 (~{SS}/OC0B/PCINT12) (io)

## ATmega644P-A15MZ
designator U?
8-bit Automotive AVR Microcontroller, 64KB Flash, 2KB EEPROM, 4KB SRAM, Automotive Grade (-40°C to +125°C), 44-Pin VQFN
footprint 44PW_N (QFN, 44-Leads, Body 7x7mm, Pitch 0.5mm, IPC Medium Density)
footprint 44PW_L (QFN, 44-Leads, Body 7x7mm, Pitch 0.5mm, IPC High Density)
footprint 44PW_M (QFN, 44-Leads, Body 7x7mm, Pitch 0.5mm, IPC Low Density)
pins: 1 PB5 (PCINT13/MOSI) (io), 2 PB6 (PCINT14/MISO) (io), 3 PB7 (PCINT15/SCK) (io), 4 ~{RESET} (in), 5 VCC (power), 6 GND (power), 7 XTAL2, 8 XTAL1, 9 PD0 (PCINT24/RXD0) (io), 10 PD1 (PCINT25/TXD0) (io), 11 PD2 (PCINT/RXD1/26/INT0) (io), 12 PD3 (PCINT/TXD1/27/INT1) (io), 13 PD4 (PCINT28/XCK1/OC1B) (io), 14 PD5 (PCINT29/OC1A) (io), 15 PD6 (PCINT30/OC2B/ICP) (io), 16 PD7 (PCINT31/OC2A) (io), 17 VCC (power), 18 GND (power), 19 PC0 (PCINT16/SCL) (io), 20 PC1 (PCINT17/SDA) (io), 21 PC2 (PCINT18/TCK) (io), 22 PC3 (PCINT19/TMS) (io), 23 PC4 (TDO/PCINT20) (io), 24 PC5 (TDI/PCINT21) (io), 25 PC6 (TOSC1/PCINT22) (io), 26 PC7 (TOSC2/PCINT23) (io), 27 AVCC (power), 28 GND (power), 29 AREF, 30 PA7 (ADC7/PCINT7) (io), 31 PA6 (ADC6/PCINT6) (io), 32 PA5 (ADC5/PCINT5) (io), 33 PA4 (ADC4/PCINT4) (io), 34 PA3 (ADC3/PCINT3) (io), 35 PA2 (ADC2/PCINT2) (io), 36 PA1 (ADC1/PCINT1) (io), 37 PA0 (ADC0/PCINT0) (io), 38 VCC (power), 39 GND (power), 40 PB0 (XCK0/T0/PCINT8) (io), 41 PB1 (T1/CLKO/PCINT9) (io), 42 PB2 (AIN0/INT2/PCINT10) (io), 43 PB3 (AIN1/OC0A/PCINT11) (io), 44 PB4 (~{SS}/OC0B/PCINT12) (io), 45 DAP (power)

## ATtiny24-15MZ
designator U?
8-bit Automotive AVR Microcontroller, 2KB Flash, 128 Bytes EEPROM, 128 Bytes SRAM, Automotive Grade (-40° to +125°C), 20-Pin VQFN
footprint 20PC_N (QFN, 20-Leads, Body 4x4mm, Pitch 0.5mm, IPC Medium Density)
footprint 20PC_L (QFN, 20-Leads, Body 4x4mm, Pitch 0.5mm, IPC High Density)
footprint 20PC_M (QFN, 20-Leads, Body 4x4mm, Pitch 0.5mm, IPC Low Density)
pins: 1 PA4 (ADC4/USCK/SCL/T1/PCINT4) (io), 2 PA3 (ADC3/T0/PCINT3) (io), 3 PA2 (ADC2/AIN1/PCINT2) (io), 4 PA1 (ADC1/AIN0/PCINT1) (io), 5 PA0 (ADC0/AREF/PCINT0) (io), 6 DNC, 7 DNC, 8 GND (power), 9 VCC (power), 10 DNC, 11 PB0 (PCINT8/XTAL1) (io), 12 PB1 (PCINT9/XTAL2) (io), 13 PB3 (PCINT11/RESET/dW) (io), 14 PB2 (PCINT10/INT0/OC0A/CKOUT) (io), 15 PA7 (PCINT7/ICP/OC0B/ADC7) (io), 16 PA6 (PCINT6/OC1A/SDA/MOSI/ADC6) (io), 17 DNC, 18 DNC, 19 DNC, 20 PA5 (ADC5/DO/MISO/OC1B/PCINT5) (io), 21 EP (power)

## ATtiny24-15SSZ
designator U?
8-bit Automotive AVR Microcontroller, 2KB Flash, 128 Bytes EEPROM, 128 Bytes SRAM, Automotive Grade (-40° to +125°C), 14-Pin SOIC
footprint 14TU_N (SOIC, 14-Leads, Body 8.6x3.9mm, Pitch 1.27mm, IPC Medium Density)
footprint 14TU_L (SOIC, 14-Leads, Body 8.6x3.9mm, Pitch 1.27mm, IPC High Density)
footprint 14TU_M (SOIC, 14-Leads, Body 8.6x3.9mm, Pitch 1.27mm, IPC Low Density)
pins: 1 VCC (power), 2 PB0 (PCINT8/XTAL1) (io), 3 PB1 (PCINT9/XTAL2) (io), 4 PB3 (PCINT11/RESET/dW) (io), 5 PB2 (PCINT10/INT0/OC0A/CKOUT) (io), 6 PA7 (PCINT7/ICP/OC0B/ADC7) (io), 7 PA6 (PCINT6/OC1A/SDA/MOSI/ADC6) (io), 8 PA5 (ADC5/DO/MISO/OC1B/PCINT5) (io), 9 PA4 (ADC4/USCK/SCL/T1/PCINT4) (io), 10 PA3 (ADC3/T0/PCINT3) (io), 11 PA2 (ADC2/AIN1/PCINT2) (io), 12 PA1 (ADC1/AIN0/PCINT1) (io), 13 PA0 (ADC0/AREF/PCINT0) (io), 14 GND (power)

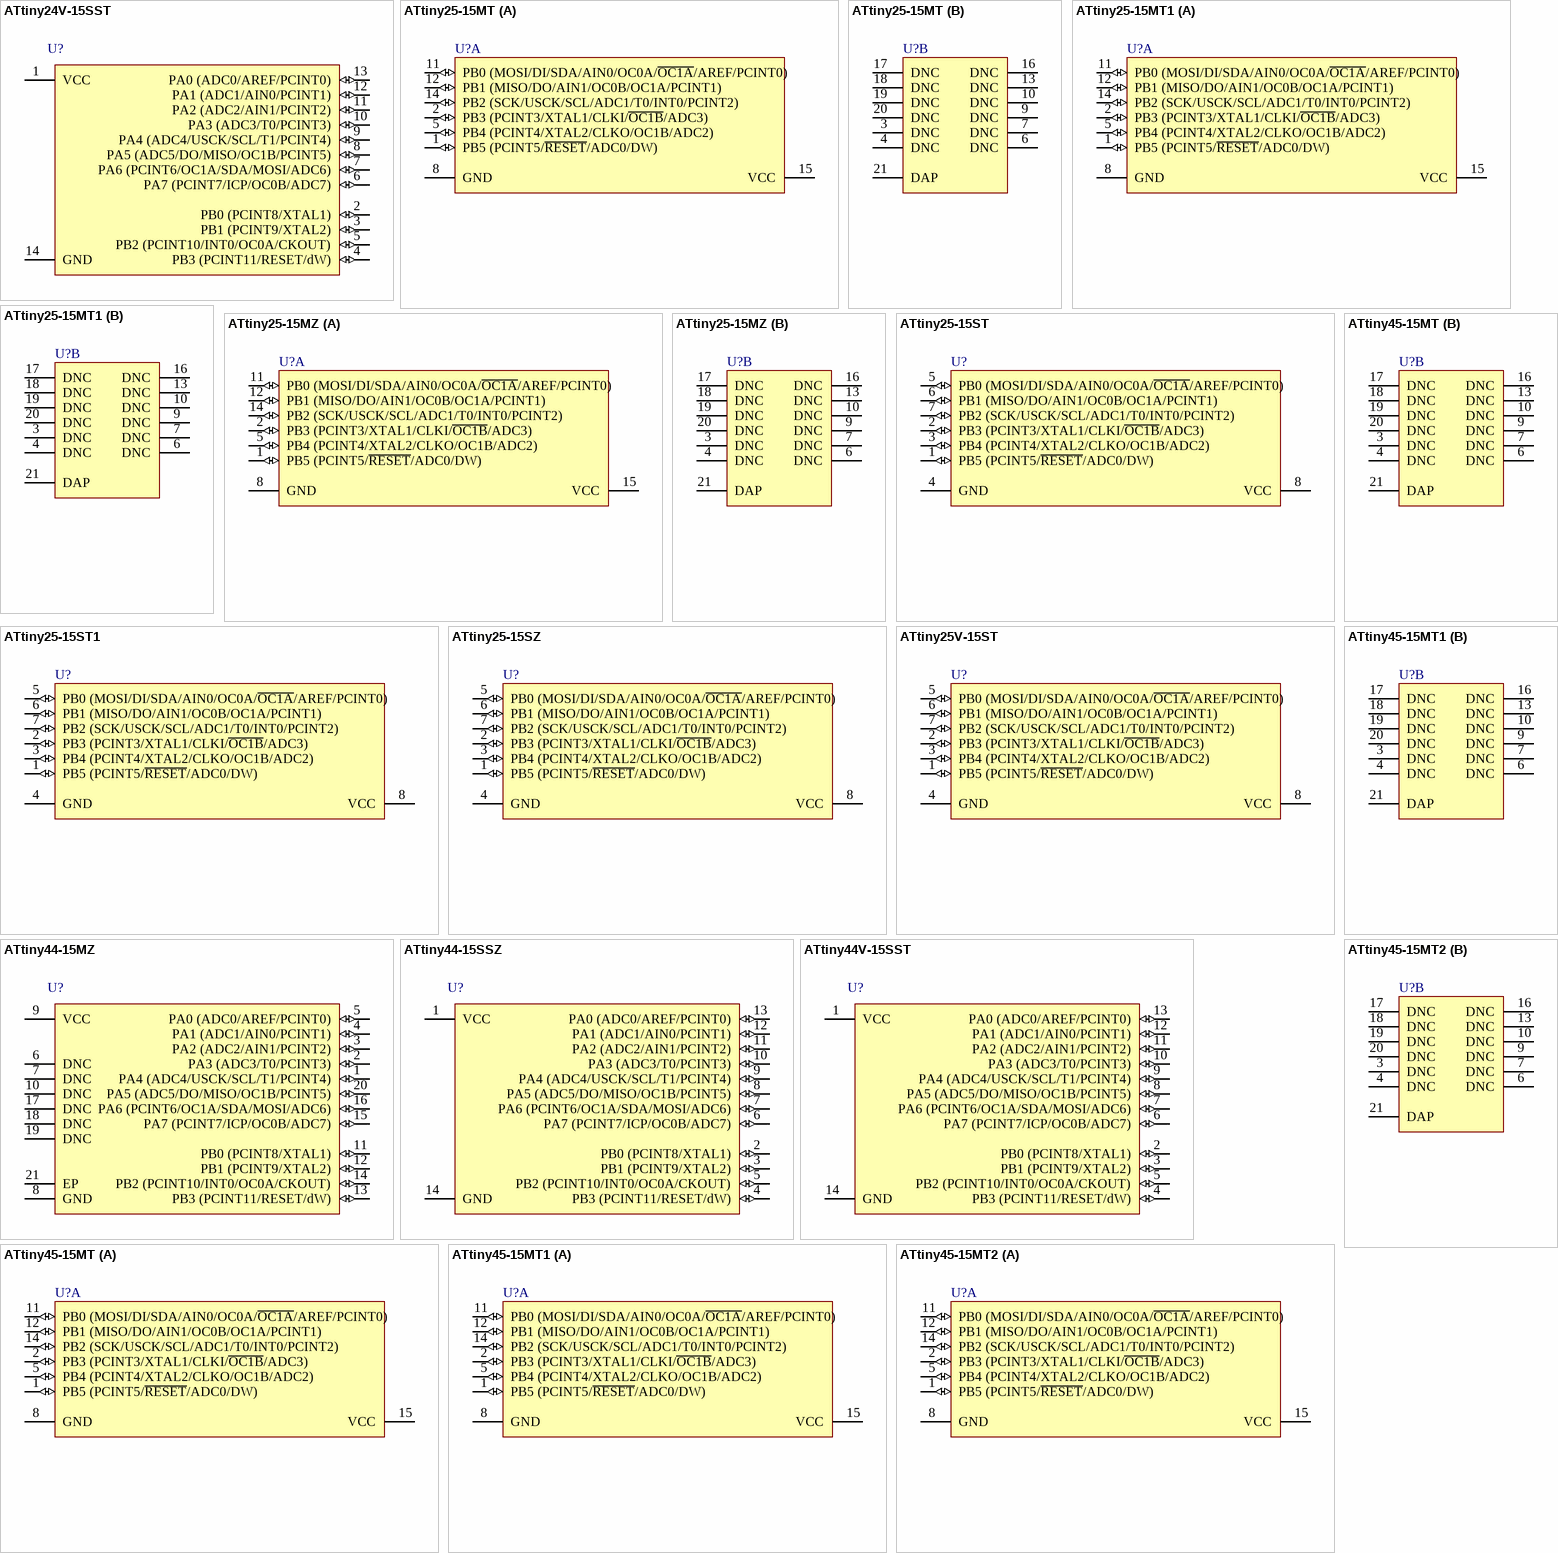
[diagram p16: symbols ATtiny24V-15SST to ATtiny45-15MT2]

## ATtiny24V-15SST
designator U?
8-bit Automotive AVR Microcontroller, 2KB Flash, 128 Bytes EEPROM, 128 Bytes SRAM, Automotive Grade (-40°C to +85°C), 14-Pin SOIC
footprint 14TU_N (SOIC, 14-Leads, Body 8.6x3.9mm, Pitch 1.27mm, IPC Medium Density)
footprint 14TU_L (SOIC, 14-Leads, Body 8.6x3.9mm, Pitch 1.27mm, IPC High Density)
footprint 14TU_M (SOIC, 14-Leads, Body 8.6x3.9mm, Pitch 1.27mm, IPC Low Density)
pins: 1 VCC (power), 2 PB0 (PCINT8/XTAL1) (io), 3 PB1 (PCINT9/XTAL2) (io), 4 PB3 (PCINT11/RESET/dW) (io), 5 PB2 (PCINT10/INT0/OC0A/CKOUT) (io), 6 PA7 (PCINT7/ICP/OC0B/ADC7) (io), 7 PA6 (PCINT6/OC1A/SDA/MOSI/ADC6) (io), 8 PA5 (ADC5/DO/MISO/OC1B/PCINT5) (io), 9 PA4 (ADC4/USCK/SCL/T1/PCINT4) (io), 10 PA3 (ADC3/T0/PCINT3) (io), 11 PA2 (ADC2/AIN1/PCINT2) (io), 12 PA1 (ADC1/AIN0/PCINT1) (io), 13 PA0 (ADC0/AREF/PCINT0) (io), 14 GND (power)

## ATtiny25-15MT
designator U?
8-bit Automotive AVR Microcontroller, 2KB Flash, 128 Bytes EEPROM, 128 Bytes SRAM, Automotive Grade (-40°C to +85°C), 20-Pin VQFN
footprint 20PC_N (QFN, 20-Leads, Body 4x4mm, Pitch 0.5mm, IPC Medium Density)
footprint 20PC_L (QFN, 20-Leads, Body 4x4mm, Pitch 0.5mm, IPC High Density)
footprint 20PC_M (QFN, 20-Leads, Body 4x4mm, Pitch 0.5mm, IPC Low Density)
part A pins: 1 PB5 (PCINT5/~{RESET}/ADC0/DW) (io), 2 PB3 (PCINT3/XTAL1/CLKI/~{OC1B}/ADC3) (io), 5 PB4 (PCINT4/XTAL2/CLKO/OC1B/ADC2) (io), 8 GND (power), 11 PB0 (MOSI/DI/SDA/AIN0/OC0A/~{OC1A}/AREF/PCINT0) (io), 12 PB1 (MISO/DO/AIN1/OC0B/OC1A/PCINT1) (io), 14 PB2 (SCK/USCK/SCL/ADC1/T0/INT0/PCINT2) (io), 15 VCC (power)
part B pins: 3 DNC, 4 DNC, 6 DNC, 7 DNC, 9 DNC, 10 DNC, 13 DNC, 16 DNC, 17 DNC, 18 DNC, 19 DNC, 20 DNC, 21 DAP

## ATtiny25-15MT1
designator U?
8-bit Automotive AVR Microcontroller, 2KB Flash, 128 Bytes EEPROM, 128 Bytes SRAM, Automotive Grade (-40°C to +105°C), 20-Pin VQFN
footprint 20PC_N (QFN, 20-Leads, Body 4x4mm, Pitch 0.5mm, IPC Medium Density)
footprint 20PC_L (QFN, 20-Leads, Body 4x4mm, Pitch 0.5mm, IPC High Density)
footprint 20PC_M (QFN, 20-Leads, Body 4x4mm, Pitch 0.5mm, IPC Low Density)
part A pins: 1 PB5 (PCINT5/~{RESET}/ADC0/DW) (io), 2 PB3 (PCINT3/XTAL1/CLKI/~{OC1B}/ADC3) (io), 5 PB4 (PCINT4/XTAL2/CLKO/OC1B/ADC2) (io), 8 GND (power), 11 PB0 (MOSI/DI/SDA/AIN0/OC0A/~{OC1A}/AREF/PCINT0) (io), 12 PB1 (MISO/DO/AIN1/OC0B/OC1A/PCINT1) (io), 14 PB2 (SCK/USCK/SCL/ADC1/T0/INT0/PCINT2) (io), 15 VCC (power)
part B pins: 3 DNC, 4 DNC, 6 DNC, 7 DNC, 9 DNC, 10 DNC, 13 DNC, 16 DNC, 17 DNC, 18 DNC, 19 DNC, 20 DNC, 21 DAP

## ATtiny25-15MZ
designator U?
8-bit Automotive AVR Microcontroller, 2KB Flash, 128 Bytes EEPROM, 128 Bytes SRAM, Automotive Grade (-40°C to +125°C), 20-Pin VQFN
footprint 20PC_N (QFN, 20-Leads, Body 4x4mm, Pitch 0.5mm, IPC Medium Density)
footprint 20PC_L (QFN, 20-Leads, Body 4x4mm, Pitch 0.5mm, IPC High Density)
footprint 20PC_M (QFN, 20-Leads, Body 4x4mm, Pitch 0.5mm, IPC Low Density)
part A pins: 1 PB5 (PCINT5/~{RESET}/ADC0/DW) (io), 2 PB3 (PCINT3/XTAL1/CLKI/~{OC1B}/ADC3) (io), 5 PB4 (PCINT4/XTAL2/CLKO/OC1B/ADC2) (io), 8 GND (power), 11 PB0 (MOSI/DI/SDA/AIN0/OC0A/~{OC1A}/AREF/PCINT0) (io), 12 PB1 (MISO/DO/AIN1/OC0B/OC1A/PCINT1) (io), 14 PB2 (SCK/USCK/SCL/ADC1/T0/INT0/PCINT2) (io), 15 VCC (power)
part B pins: 3 DNC, 4 DNC, 6 DNC, 7 DNC, 9 DNC, 10 DNC, 13 DNC, 16 DNC, 17 DNC, 18 DNC, 19 DNC, 20 DNC, 21 DAP

## ATtiny25-15ST
designator U?
8-bit Automotive AVR Microcontroller, 2KB Flash, 128 Bytes EEPROM, 128 Bytes SRAM, Automotive Grade (-40°C to +85°C), 8-Pin SOIC
footprint T5_N (SOP, 8-Leads, Body 5.2x5.3mm, Pitch 1.27mm, IPC Medium Density)
footprint T5_L (SOP, 8-Leads, Body 5.2x5.3mm, Pitch 1.27mm, IPC High Density)
footprint T5_M (SOP, 8-Leads, Body 5.2x5.3mm, Pitch 1.27mm, IPC Low Density)
pins: 1 PB5 (PCINT5/~{RESET}/ADC0/DW) (io), 2 PB3 (PCINT3/XTAL1/CLKI/~{OC1B}/ADC3) (io), 3 PB4 (PCINT4/XTAL2/CLKO/OC1B/ADC2) (io), 4 GND (power), 5 PB0 (MOSI/DI/SDA/AIN0/OC0A/~{OC1A}/AREF/PCINT0) (io), 6 PB1 (MISO/DO/AIN1/OC0B/OC1A/PCINT1) (io), 7 PB2 (SCK/USCK/SCL/ADC1/T0/INT0/PCINT2) (io), 8 VCC (power)

## ATtiny25-15ST1
designator U?
8-bit Automotive AVR Microcontroller, 2KB Flash, 128 Bytes EEPROM, 128 Bytes SRAM, Automotive Grade (-40°C to +105°C), 8-Pin SOIC
footprint T5_N (SOP, 8-Leads, Body 5.2x5.3mm, Pitch 1.27mm, IPC Medium Density)
footprint T5_L (SOP, 8-Leads, Body 5.2x5.3mm, Pitch 1.27mm, IPC High Density)
footprint T5_M (SOP, 8-Leads, Body 5.2x5.3mm, Pitch 1.27mm, IPC Low Density)
pins: 1 PB5 (PCINT5/~{RESET}/ADC0/DW) (io), 2 PB3 (PCINT3/XTAL1/CLKI/~{OC1B}/ADC3) (io), 3 PB4 (PCINT4/XTAL2/CLKO/OC1B/ADC2) (io), 4 GND (power), 5 PB0 (MOSI/DI/SDA/AIN0/OC0A/~{OC1A}/AREF/PCINT0) (io), 6 PB1 (MISO/DO/AIN1/OC0B/OC1A/PCINT1) (io), 7 PB2 (SCK/USCK/SCL/ADC1/T0/INT0/PCINT2) (io), 8 VCC (power)

## ATtiny25-15SZ
designator U?
8-bit Automotive AVR Microcontroller, 2KB Flash, 128 Bytes EEPROM, 128 Bytes SRAM, Automotive Grade (-40°C to +125°C), 8-Pin SOIC
footprint T5_N (SOP, 8-Leads, Body 5.2x5.3mm, Pitch 1.27mm, IPC Medium Density)
footprint T5_L (SOP, 8-Leads, Body 5.2x5.3mm, Pitch 1.27mm, IPC High Density)
footprint T5_M (SOP, 8-Leads, Body 5.2x5.3mm, Pitch 1.27mm, IPC Low Density)
pins: 1 PB5 (PCINT5/~{RESET}/ADC0/DW) (io), 2 PB3 (PCINT3/XTAL1/CLKI/~{OC1B}/ADC3) (io), 3 PB4 (PCINT4/XTAL2/CLKO/OC1B/ADC2) (io), 4 GND (power), 5 PB0 (MOSI/DI/SDA/AIN0/OC0A/~{OC1A}/AREF/PCINT0) (io), 6 PB1 (MISO/DO/AIN1/OC0B/OC1A/PCINT1) (io), 7 PB2 (SCK/USCK/SCL/ADC1/T0/INT0/PCINT2) (io), 8 VCC (power)

## ATtiny25V-15ST
designator U?
8-bit Automotive AVR Microcontroller, 1.8-3.6V, 2KB Flash, 128 Bytes EEPROM, 128 Bytes SRAM, Automotive Grade (-40°C to +85°C), 8-Pin SOIC
footprint T5_N (SOP, 8-Leads, Body 5.2x5.3mm, Pitch 1.27mm, IPC Medium Density)
footprint T5_L (SOP, 8-Leads, Body 5.2x5.3mm, Pitch 1.27mm, IPC High Density)
footprint T5_M (SOP, 8-Leads, Body 5.2x5.3mm, Pitch 1.27mm, IPC Low Density)
pins: 1 PB5 (PCINT5/~{RESET}/ADC0/DW) (io), 2 PB3 (PCINT3/XTAL1/CLKI/~{OC1B}/ADC3) (io), 3 PB4 (PCINT4/XTAL2/CLKO/OC1B/ADC2) (io), 4 GND (power), 5 PB0 (MOSI/DI/SDA/AIN0/OC0A/~{OC1A}/AREF/PCINT0) (io), 6 PB1 (MISO/DO/AIN1/OC0B/OC1A/PCINT1) (io), 7 PB2 (SCK/USCK/SCL/ADC1/T0/INT0/PCINT2) (io), 8 VCC (power)

## ATtiny44-15MZ
designator U?
8-bit Automotive AVR Microcontroller, 4KB Flash, 256 Bytes EEPROM, 256 Bytes SRAM, Automotive Grade (-40° to +125°C), 20-Pin VQFN
footprint 20PC_N (QFN, 20-Leads, Body 4x4mm, Pitch 0.5mm, IPC Medium Density)
footprint 20PC_L (QFN, 20-Leads, Body 4x4mm, Pitch 0.5mm, IPC High Density)
footprint 20PC_M (QFN, 20-Leads, Body 4x4mm, Pitch 0.5mm, IPC Low Density)
pins: 1 PA4 (ADC4/USCK/SCL/T1/PCINT4) (io), 2 PA3 (ADC3/T0/PCINT3) (io), 3 PA2 (ADC2/AIN1/PCINT2) (io), 4 PA1 (ADC1/AIN0/PCINT1) (io), 5 PA0 (ADC0/AREF/PCINT0) (io), 6 DNC, 7 DNC, 8 GND (power), 9 VCC (power), 10 DNC, 11 PB0 (PCINT8/XTAL1) (io), 12 PB1 (PCINT9/XTAL2) (io), 13 PB3 (PCINT11/RESET/dW) (io), 14 PB2 (PCINT10/INT0/OC0A/CKOUT) (io), 15 PA7 (PCINT7/ICP/OC0B/ADC7) (io), 16 PA6 (PCINT6/OC1A/SDA/MOSI/ADC6) (io), 17 DNC, 18 DNC, 19 DNC, 20 PA5 (ADC5/DO/MISO/OC1B/PCINT5) (io), 21 EP (power)

## ATtiny44-15SSZ
designator U?
8-bit Automotive AVR Microcontroller, 4KB Flash, 256 Bytes EEPROM, 256 Bytes SRAM, Automotive Grade (-40° to +125°C), 14-Pin SOIC
footprint 14TU_N (SOIC, 14-Leads, Body 8.6x3.9mm, Pitch 1.27mm, IPC Medium Density)
footprint 14TU_L (SOIC, 14-Leads, Body 8.6x3.9mm, Pitch 1.27mm, IPC High Density)
footprint 14TU_M (SOIC, 14-Leads, Body 8.6x3.9mm, Pitch 1.27mm, IPC Low Density)
pins: 1 VCC (power), 2 PB0 (PCINT8/XTAL1) (io), 3 PB1 (PCINT9/XTAL2) (io), 4 PB3 (PCINT11/RESET/dW) (io), 5 PB2 (PCINT10/INT0/OC0A/CKOUT) (io), 6 PA7 (PCINT7/ICP/OC0B/ADC7) (io), 7 PA6 (PCINT6/OC1A/SDA/MOSI/ADC6) (io), 8 PA5 (ADC5/DO/MISO/OC1B/PCINT5) (io), 9 PA4 (ADC4/USCK/SCL/T1/PCINT4) (io), 10 PA3 (ADC3/T0/PCINT3) (io), 11 PA2 (ADC2/AIN1/PCINT2) (io), 12 PA1 (ADC1/AIN0/PCINT1) (io), 13 PA0 (ADC0/AREF/PCINT0) (io), 14 GND (power)

## ATtiny44V-15SST
designator U?
8-bit Automotive AVR Microcontroller, 4KB Flash, 256 Bytes EEPROM, 256 Bytes SRAM, Automotive Grade (-40°C to +85°C), 14-Pin SOIC
footprint 14TU_N (SOIC, 14-Leads, Body 8.6x3.9mm, Pitch 1.27mm, IPC Medium Density)
footprint 14TU_L (SOIC, 14-Leads, Body 8.6x3.9mm, Pitch 1.27mm, IPC High Density)
footprint 14TU_M (SOIC, 14-Leads, Body 8.6x3.9mm, Pitch 1.27mm, IPC Low Density)
pins: 1 VCC (power), 2 PB0 (PCINT8/XTAL1) (io), 3 PB1 (PCINT9/XTAL2) (io), 4 PB3 (PCINT11/RESET/dW) (io), 5 PB2 (PCINT10/INT0/OC0A/CKOUT) (io), 6 PA7 (PCINT7/ICP/OC0B/ADC7) (io), 7 PA6 (PCINT6/OC1A/SDA/MOSI/ADC6) (io), 8 PA5 (ADC5/DO/MISO/OC1B/PCINT5) (io), 9 PA4 (ADC4/USCK/SCL/T1/PCINT4) (io), 10 PA3 (ADC3/T0/PCINT3) (io), 11 PA2 (ADC2/AIN1/PCINT2) (io), 12 PA1 (ADC1/AIN0/PCINT1) (io), 13 PA0 (ADC0/AREF/PCINT0) (io), 14 GND (power)

## ATtiny45-15MT
designator U?
8-bit Automotive AVR Microcontroller, 4KB Flash, 256 Bytes EEPROM, 256 Bytes SRAM, Automotive Grade (-40°C to +85°C), 20-Pin VQFN
footprint 20PC_N (QFN, 20-Leads, Body 4x4mm, Pitch 0.5mm, IPC Medium Density)
footprint 20PC_L (QFN, 20-Leads, Body 4x4mm, Pitch 0.5mm, IPC High Density)
footprint 20PC_M (QFN, 20-Leads, Body 4x4mm, Pitch 0.5mm, IPC Low Density)
part A pins: 1 PB5 (PCINT5/~{RESET}/ADC0/DW) (io), 2 PB3 (PCINT3/XTAL1/CLKI/~{OC1B}/ADC3) (io), 5 PB4 (PCINT4/XTAL2/CLKO/OC1B/ADC2) (io), 8 GND (power), 11 PB0 (MOSI/DI/SDA/AIN0/OC0A/~{OC1A}/AREF/PCINT0) (io), 12 PB1 (MISO/DO/AIN1/OC0B/OC1A/PCINT1) (io), 14 PB2 (SCK/USCK/SCL/ADC1/T0/INT0/PCINT2) (io), 15 VCC (power)
part B pins: 3 DNC, 4 DNC, 6 DNC, 7 DNC, 9 DNC, 10 DNC, 13 DNC, 16 DNC, 17 DNC, 18 DNC, 19 DNC, 20 DNC, 21 DAP

## ATtiny45-15MT1
designator U?
8-bit Automotive AVR Microcontroller, 4KB Flash, 256 Bytes EEPROM, 256 Bytes SRAM, Automotive Grade (-40°C to +105°C), 20-Pin VQFN
footprint 20PC_N (QFN, 20-Leads, Body 4x4mm, Pitch 0.5mm, IPC Medium Density)
footprint 20PC_L (QFN, 20-Leads, Body 4x4mm, Pitch 0.5mm, IPC High Density)
footprint 20PC_M (QFN, 20-Leads, Body 4x4mm, Pitch 0.5mm, IPC Low Density)
part A pins: 1 PB5 (PCINT5/~{RESET}/ADC0/DW) (io), 2 PB3 (PCINT3/XTAL1/CLKI/~{OC1B}/ADC3) (io), 5 PB4 (PCINT4/XTAL2/CLKO/OC1B/ADC2) (io), 8 GND (power), 11 PB0 (MOSI/DI/SDA/AIN0/OC0A/~{OC1A}/AREF/PCINT0) (io), 12 PB1 (MISO/DO/AIN1/OC0B/OC1A/PCINT1) (io), 14 PB2 (SCK/USCK/SCL/ADC1/T0/INT0/PCINT2) (io), 15 VCC (power)
part B pins: 3 DNC, 4 DNC, 6 DNC, 7 DNC, 9 DNC, 10 DNC, 13 DNC, 16 DNC, 17 DNC, 18 DNC, 19 DNC, 20 DNC, 21 DAP

## ATtiny45-15MT2
designator U?
8-bit Automotive AVR Microcontroller, 4KB Flash, 256 Bytes EEPROM, 256 Bytes SRAM, Extended Grade (-40°C to +150°C), 20-Pin VQFN
footprint 20PC_N (QFN, 20-Leads, Body 4x4mm, Pitch 0.5mm, IPC Medium Density)
footprint 20PC_L (QFN, 20-Leads, Body 4x4mm, Pitch 0.5mm, IPC High Density)
footprint 20PC_M (QFN, 20-Leads, Body 4x4mm, Pitch 0.5mm, IPC Low Density)
part A pins: 1 PB5 (PCINT5/~{RESET}/ADC0/DW) (io), 2 PB3 (PCINT3/XTAL1/CLKI/~{OC1B}/ADC3) (io), 5 PB4 (PCINT4/XTAL2/CLKO/OC1B/ADC2) (io), 8 GND (power), 11 PB0 (MOSI/DI/SDA/AIN0/OC0A/~{OC1A}/AREF/PCINT0) (io), 12 PB1 (MISO/DO/AIN1/OC0B/OC1A/PCINT1) (io), 14 PB2 (SCK/USCK/SCL/ADC1/T0/INT0/PCINT2) (io), 15 VCC (power)
part B pins: 3 DNC, 4 DNC, 6 DNC, 7 DNC, 9 DNC, 10 DNC, 13 DNC, 16 DNC, 17 DNC, 18 DNC, 19 DNC, 20 DNC, 21 DAP

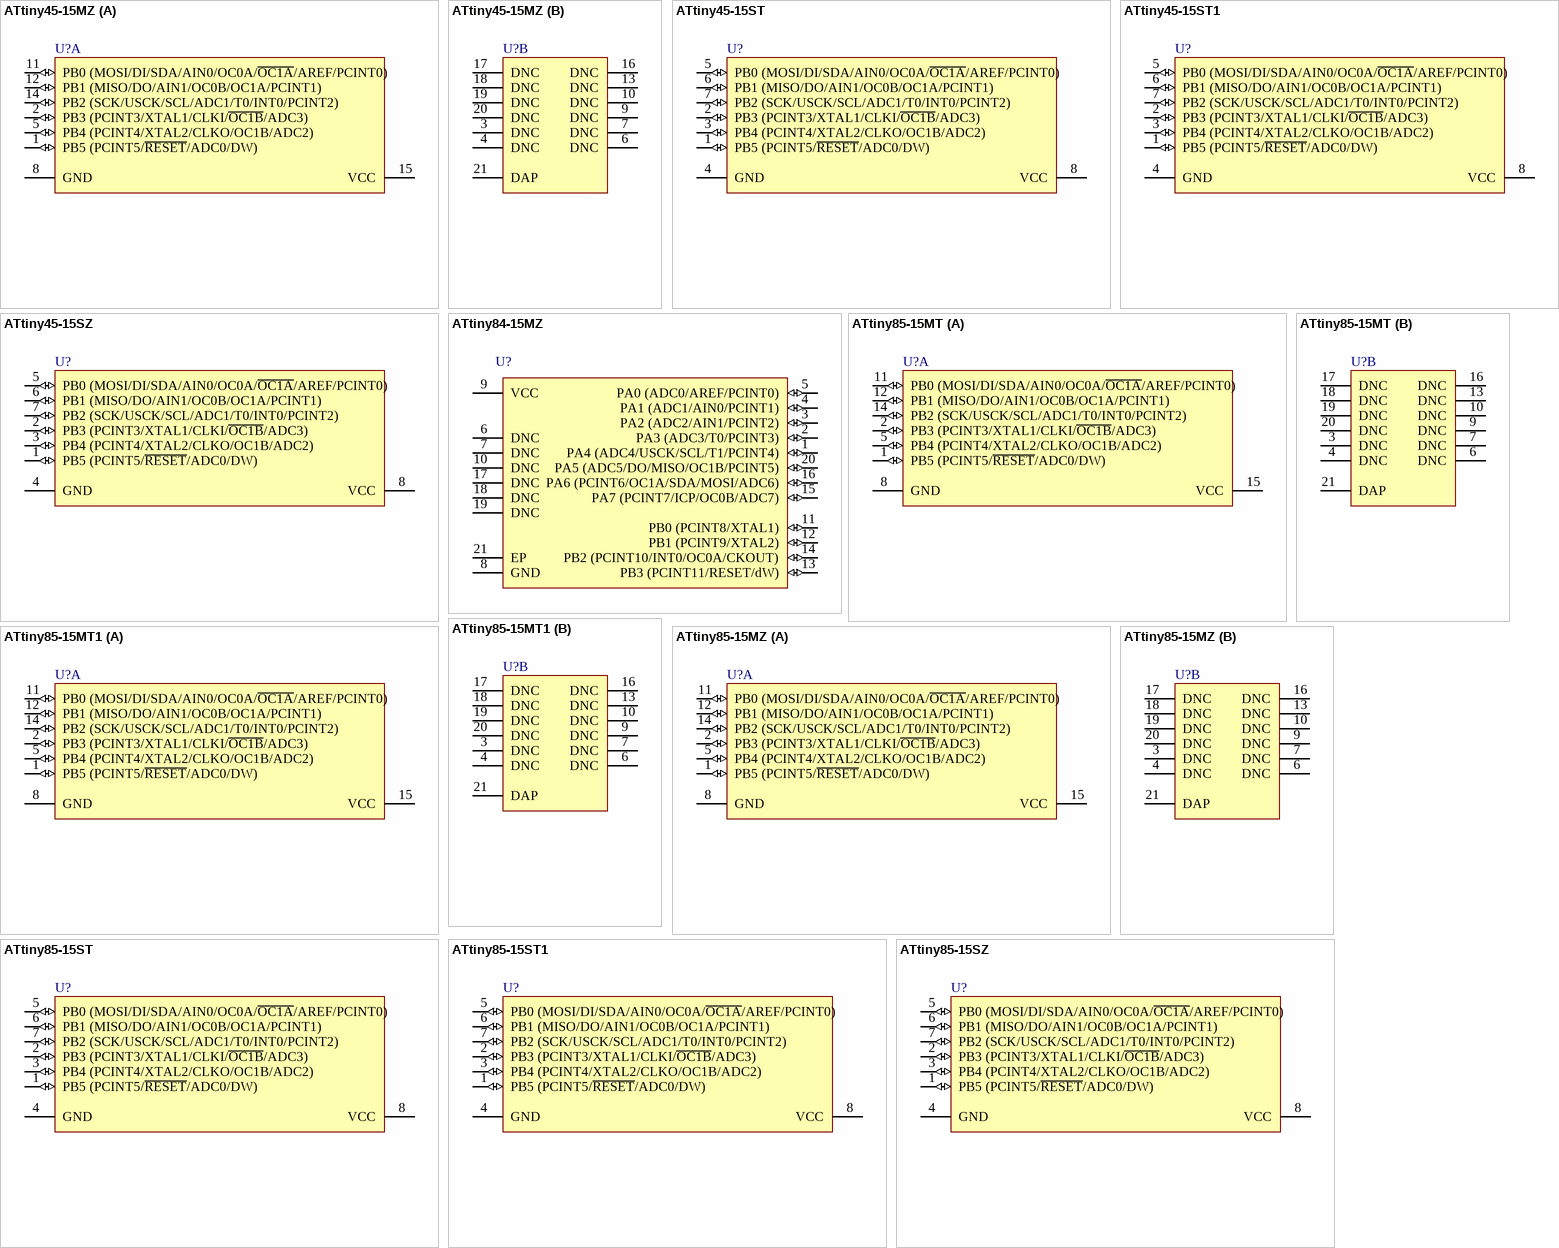
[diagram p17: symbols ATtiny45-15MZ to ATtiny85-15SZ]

## ATtiny45-15MZ
designator U?
8-bit Automotive AVR Microcontroller, 4KB Flash, 256 Bytes EEPROM, 256 Bytes SRAM, Automotive Grade (-40°C to +125°C), 20-Pin VQFN
footprint 20PC_N (QFN, 20-Leads, Body 4x4mm, Pitch 0.5mm, IPC Medium Density)
footprint 20PC_L (QFN, 20-Leads, Body 4x4mm, Pitch 0.5mm, IPC High Density)
footprint 20PC_M (QFN, 20-Leads, Body 4x4mm, Pitch 0.5mm, IPC Low Density)
part A pins: 1 PB5 (PCINT5/~{RESET}/ADC0/DW) (io), 2 PB3 (PCINT3/XTAL1/CLKI/~{OC1B}/ADC3) (io), 5 PB4 (PCINT4/XTAL2/CLKO/OC1B/ADC2) (io), 8 GND (power), 11 PB0 (MOSI/DI/SDA/AIN0/OC0A/~{OC1A}/AREF/PCINT0) (io), 12 PB1 (MISO/DO/AIN1/OC0B/OC1A/PCINT1) (io), 14 PB2 (SCK/USCK/SCL/ADC1/T0/INT0/PCINT2) (io), 15 VCC (power)
part B pins: 3 DNC, 4 DNC, 6 DNC, 7 DNC, 9 DNC, 10 DNC, 13 DNC, 16 DNC, 17 DNC, 18 DNC, 19 DNC, 20 DNC, 21 DAP

## ATtiny45-15ST
designator U?
8-bit Automotive AVR Microcontroller, 4KB Flash, 256 Bytes EEPROM, 256 Bytes SRAM, Automotive Grade (-40°C to +85°C), 8-Pin SOIC
footprint T5_N (SOP, 8-Leads, Body 5.2x5.3mm, Pitch 1.27mm, IPC Medium Density)
footprint T5_L (SOP, 8-Leads, Body 5.2x5.3mm, Pitch 1.27mm, IPC High Density)
footprint T5_M (SOP, 8-Leads, Body 5.2x5.3mm, Pitch 1.27mm, IPC Low Density)
pins: 1 PB5 (PCINT5/~{RESET}/ADC0/DW) (io), 2 PB3 (PCINT3/XTAL1/CLKI/~{OC1B}/ADC3) (io), 3 PB4 (PCINT4/XTAL2/CLKO/OC1B/ADC2) (io), 4 GND (power), 5 PB0 (MOSI/DI/SDA/AIN0/OC0A/~{OC1A}/AREF/PCINT0) (io), 6 PB1 (MISO/DO/AIN1/OC0B/OC1A/PCINT1) (io), 7 PB2 (SCK/USCK/SCL/ADC1/T0/INT0/PCINT2) (io), 8 VCC (power)

## ATtiny45-15ST1
designator U?
8-bit Automotive AVR Microcontroller, 4KB Flash, 256 Bytes EEPROM, 256 Bytes SRAM, Automotive Grade (-40°C to +105°C), 8-Pin SOIC
footprint T5_N (SOP, 8-Leads, Body 5.2x5.3mm, Pitch 1.27mm, IPC Medium Density)
footprint T5_L (SOP, 8-Leads, Body 5.2x5.3mm, Pitch 1.27mm, IPC High Density)
footprint T5_M (SOP, 8-Leads, Body 5.2x5.3mm, Pitch 1.27mm, IPC Low Density)
pins: 1 PB5 (PCINT5/~{RESET}/ADC0/DW) (io), 2 PB3 (PCINT3/XTAL1/CLKI/~{OC1B}/ADC3) (io), 3 PB4 (PCINT4/XTAL2/CLKO/OC1B/ADC2) (io), 4 GND (power), 5 PB0 (MOSI/DI/SDA/AIN0/OC0A/~{OC1A}/AREF/PCINT0) (io), 6 PB1 (MISO/DO/AIN1/OC0B/OC1A/PCINT1) (io), 7 PB2 (SCK/USCK/SCL/ADC1/T0/INT0/PCINT2) (io), 8 VCC (power)

## ATtiny45-15SZ
designator U?
8-bit Automotive AVR Microcontroller, 4KB Flash, 256 Bytes EEPROM, 256 Bytes SRAM, Automotive Grade (-40°C to +125°C), 8-Pin SOIC
footprint T5_N (SOP, 8-Leads, Body 5.2x5.3mm, Pitch 1.27mm, IPC Medium Density)
footprint T5_L (SOP, 8-Leads, Body 5.2x5.3mm, Pitch 1.27mm, IPC High Density)
footprint T5_M (SOP, 8-Leads, Body 5.2x5.3mm, Pitch 1.27mm, IPC Low Density)
pins: 1 PB5 (PCINT5/~{RESET}/ADC0/DW) (io), 2 PB3 (PCINT3/XTAL1/CLKI/~{OC1B}/ADC3) (io), 3 PB4 (PCINT4/XTAL2/CLKO/OC1B/ADC2) (io), 4 GND (power), 5 PB0 (MOSI/DI/SDA/AIN0/OC0A/~{OC1A}/AREF/PCINT0) (io), 6 PB1 (MISO/DO/AIN1/OC0B/OC1A/PCINT1) (io), 7 PB2 (SCK/USCK/SCL/ADC1/T0/INT0/PCINT2) (io), 8 VCC (power)

## ATtiny84-15MZ
designator U?
8-bit Automotive AVR Microcontroller, 8KB Flash, 512 Bytes EEPROM, 512 Bytes SRAM, Automotive Grade (-40° to +125°C), 20-Pin VQFN
footprint 20PC_N (QFN, 20-Leads, Body 4x4mm, Pitch 0.5mm, IPC Medium Density)
footprint 20PC_L (QFN, 20-Leads, Body 4x4mm, Pitch 0.5mm, IPC High Density)
footprint 20PC_M (QFN, 20-Leads, Body 4x4mm, Pitch 0.5mm, IPC Low Density)
pins: 1 PA4 (ADC4/USCK/SCL/T1/PCINT4) (io), 2 PA3 (ADC3/T0/PCINT3) (io), 3 PA2 (ADC2/AIN1/PCINT2) (io), 4 PA1 (ADC1/AIN0/PCINT1) (io), 5 PA0 (ADC0/AREF/PCINT0) (io), 6 DNC, 7 DNC, 8 GND (power), 9 VCC (power), 10 DNC, 11 PB0 (PCINT8/XTAL1) (io), 12 PB1 (PCINT9/XTAL2) (io), 13 PB3 (PCINT11/RESET/dW) (io), 14 PB2 (PCINT10/INT0/OC0A/CKOUT) (io), 15 PA7 (PCINT7/ICP/OC0B/ADC7) (io), 16 PA6 (PCINT6/OC1A/SDA/MOSI/ADC6) (io), 17 DNC, 18 DNC, 19 DNC, 20 PA5 (ADC5/DO/MISO/OC1B/PCINT5) (io), 21 EP (power)

## ATtiny85-15MT
designator U?
8-bit Automotive AVR Microcontroller, 8KB Flash, 512 Bytes EEPROM, 512 Bytes SRAM, Automotive Grade (-40°C to +85°C), 20-Pin VQFN
footprint 20PC_N (QFN, 20-Leads, Body 4x4mm, Pitch 0.5mm, IPC Medium Density)
footprint 20PC_L (QFN, 20-Leads, Body 4x4mm, Pitch 0.5mm, IPC High Density)
footprint 20PC_M (QFN, 20-Leads, Body 4x4mm, Pitch 0.5mm, IPC Low Density)
part A pins: 1 PB5 (PCINT5/~{RESET}/ADC0/DW) (io), 2 PB3 (PCINT3/XTAL1/CLKI/~{OC1B}/ADC3) (io), 5 PB4 (PCINT4/XTAL2/CLKO/OC1B/ADC2) (io), 8 GND (power), 11 PB0 (MOSI/DI/SDA/AIN0/OC0A/~{OC1A}/AREF/PCINT0) (io), 12 PB1 (MISO/DO/AIN1/OC0B/OC1A/PCINT1) (io), 14 PB2 (SCK/USCK/SCL/ADC1/T0/INT0/PCINT2) (io), 15 VCC (power)
part B pins: 3 DNC, 4 DNC, 6 DNC, 7 DNC, 9 DNC, 10 DNC, 13 DNC, 16 DNC, 17 DNC, 18 DNC, 19 DNC, 20 DNC, 21 DAP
